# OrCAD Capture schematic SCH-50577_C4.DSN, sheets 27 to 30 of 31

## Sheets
27 26 Interface/JTAG: size C
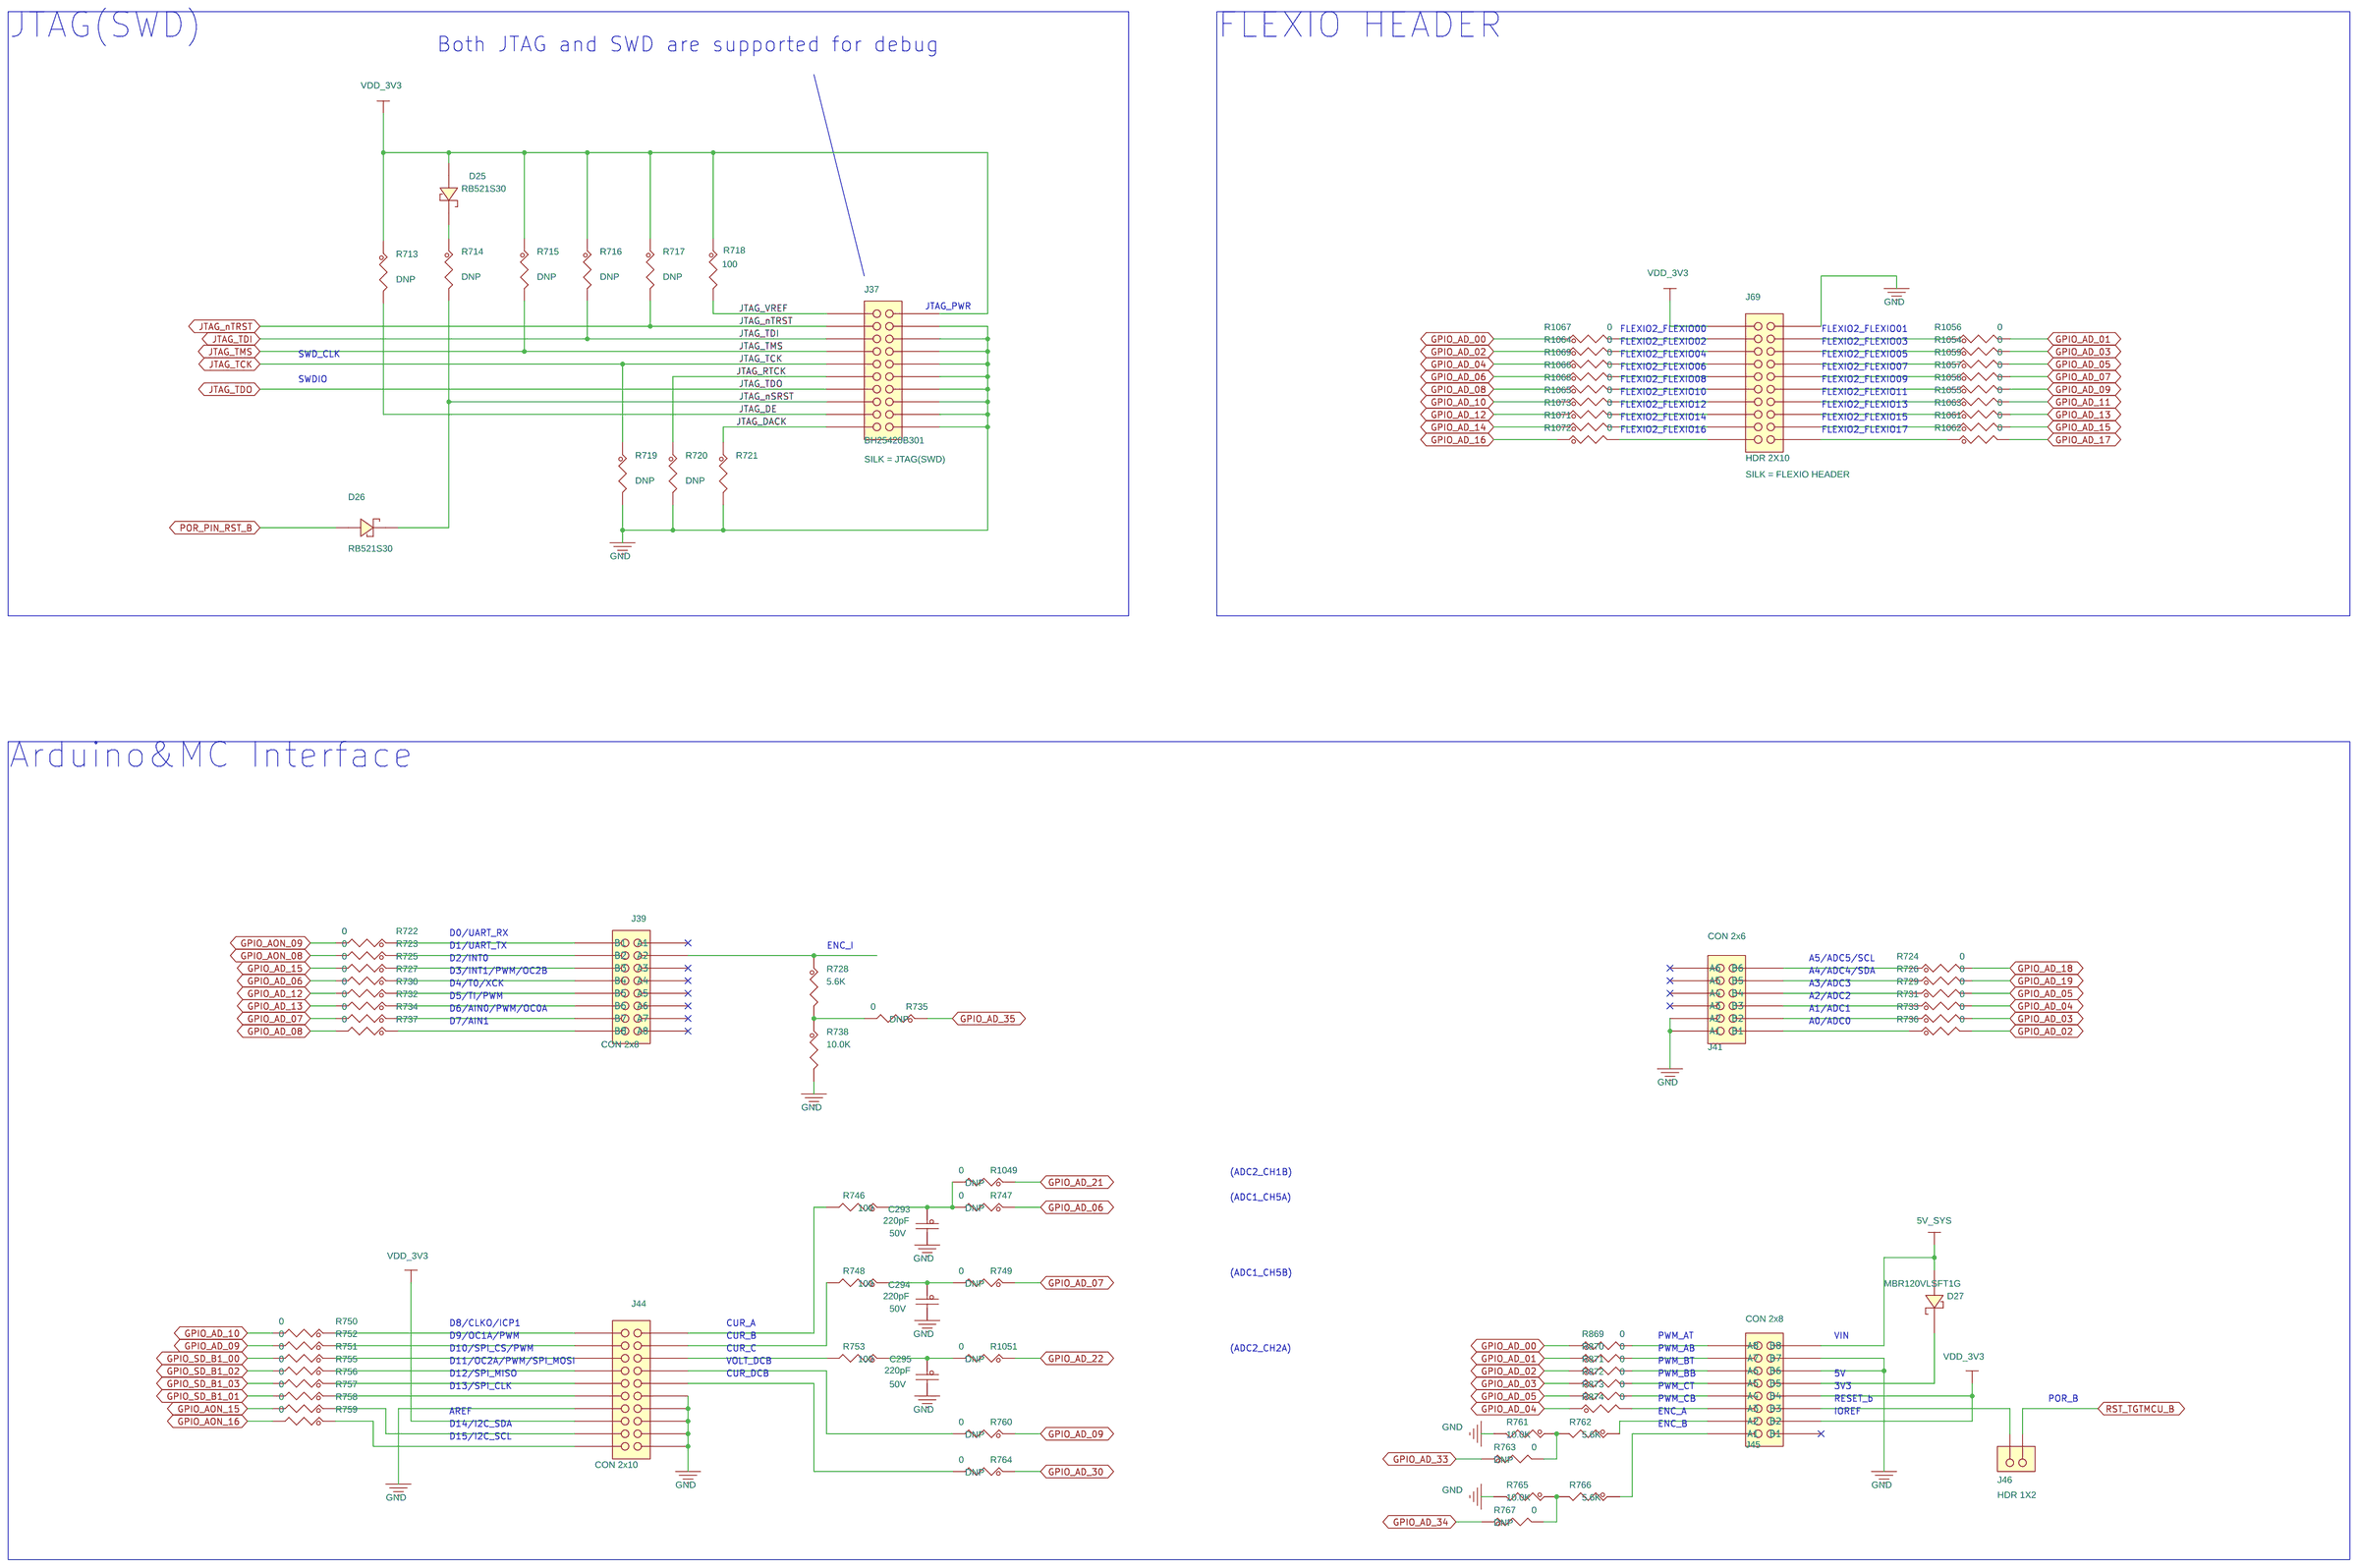
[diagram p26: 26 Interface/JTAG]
28 11 SDRAM_opt/HyperRAM: size C
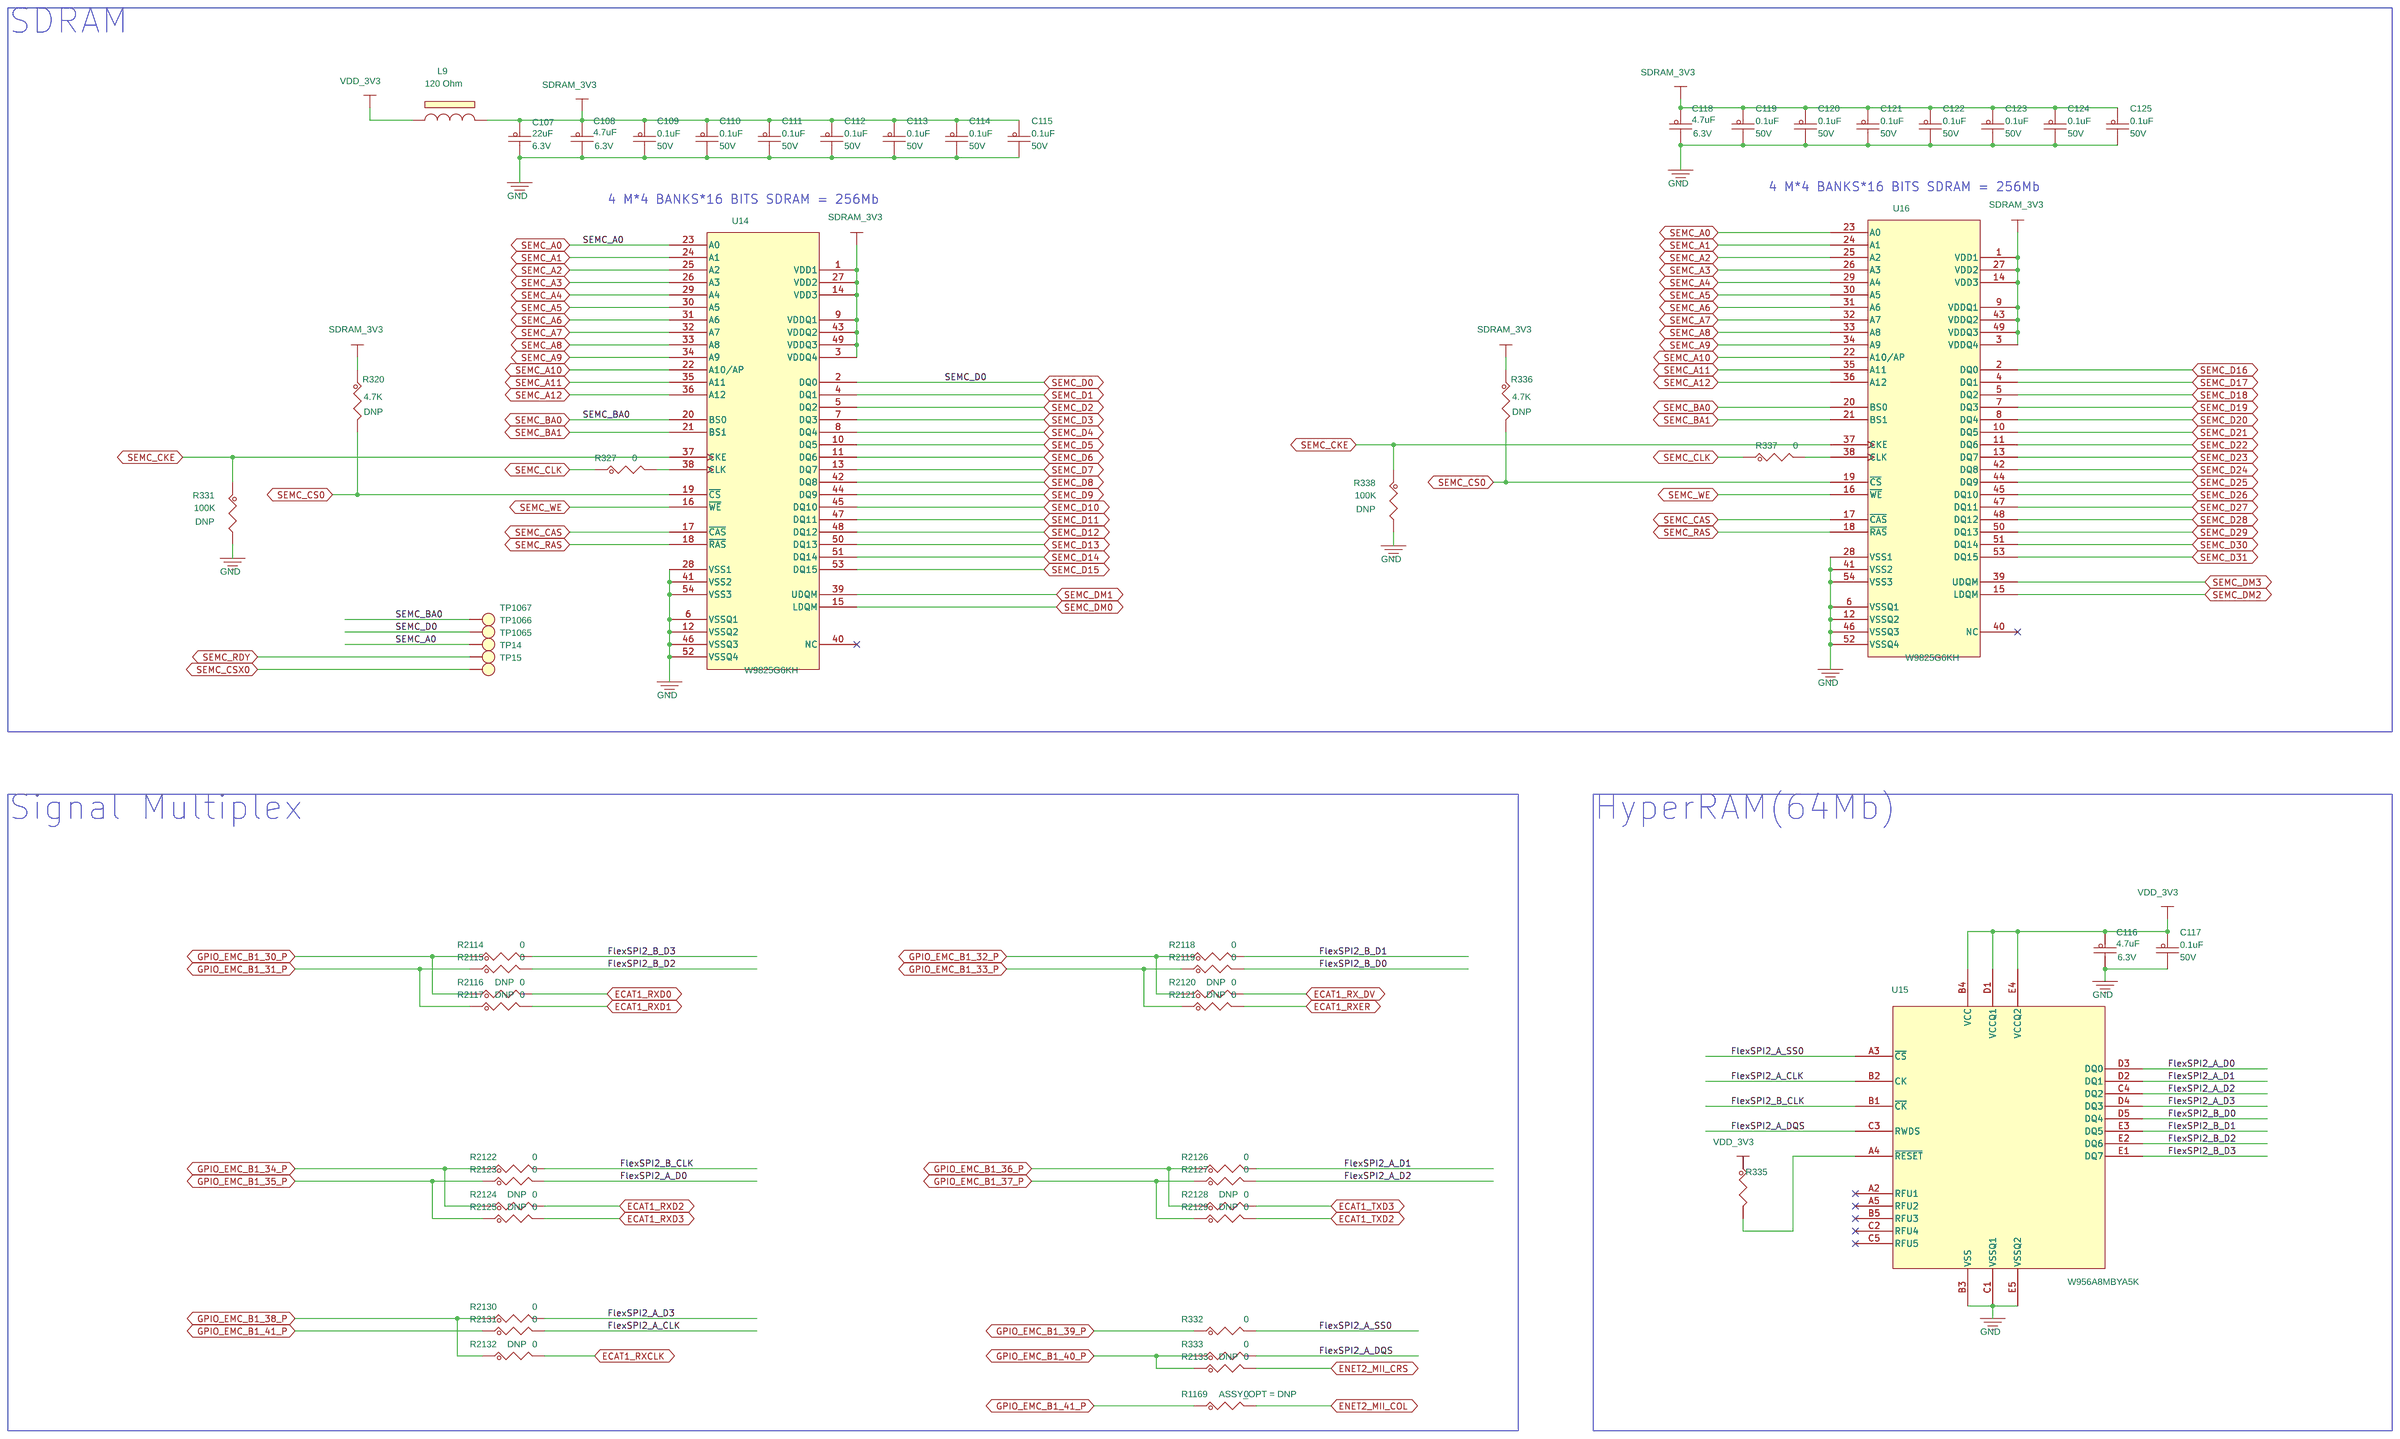
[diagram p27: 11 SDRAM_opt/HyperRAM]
29 20 RGMII/MII/RMII DC: size C; note: SCH-55220, PDF:SPF-55220
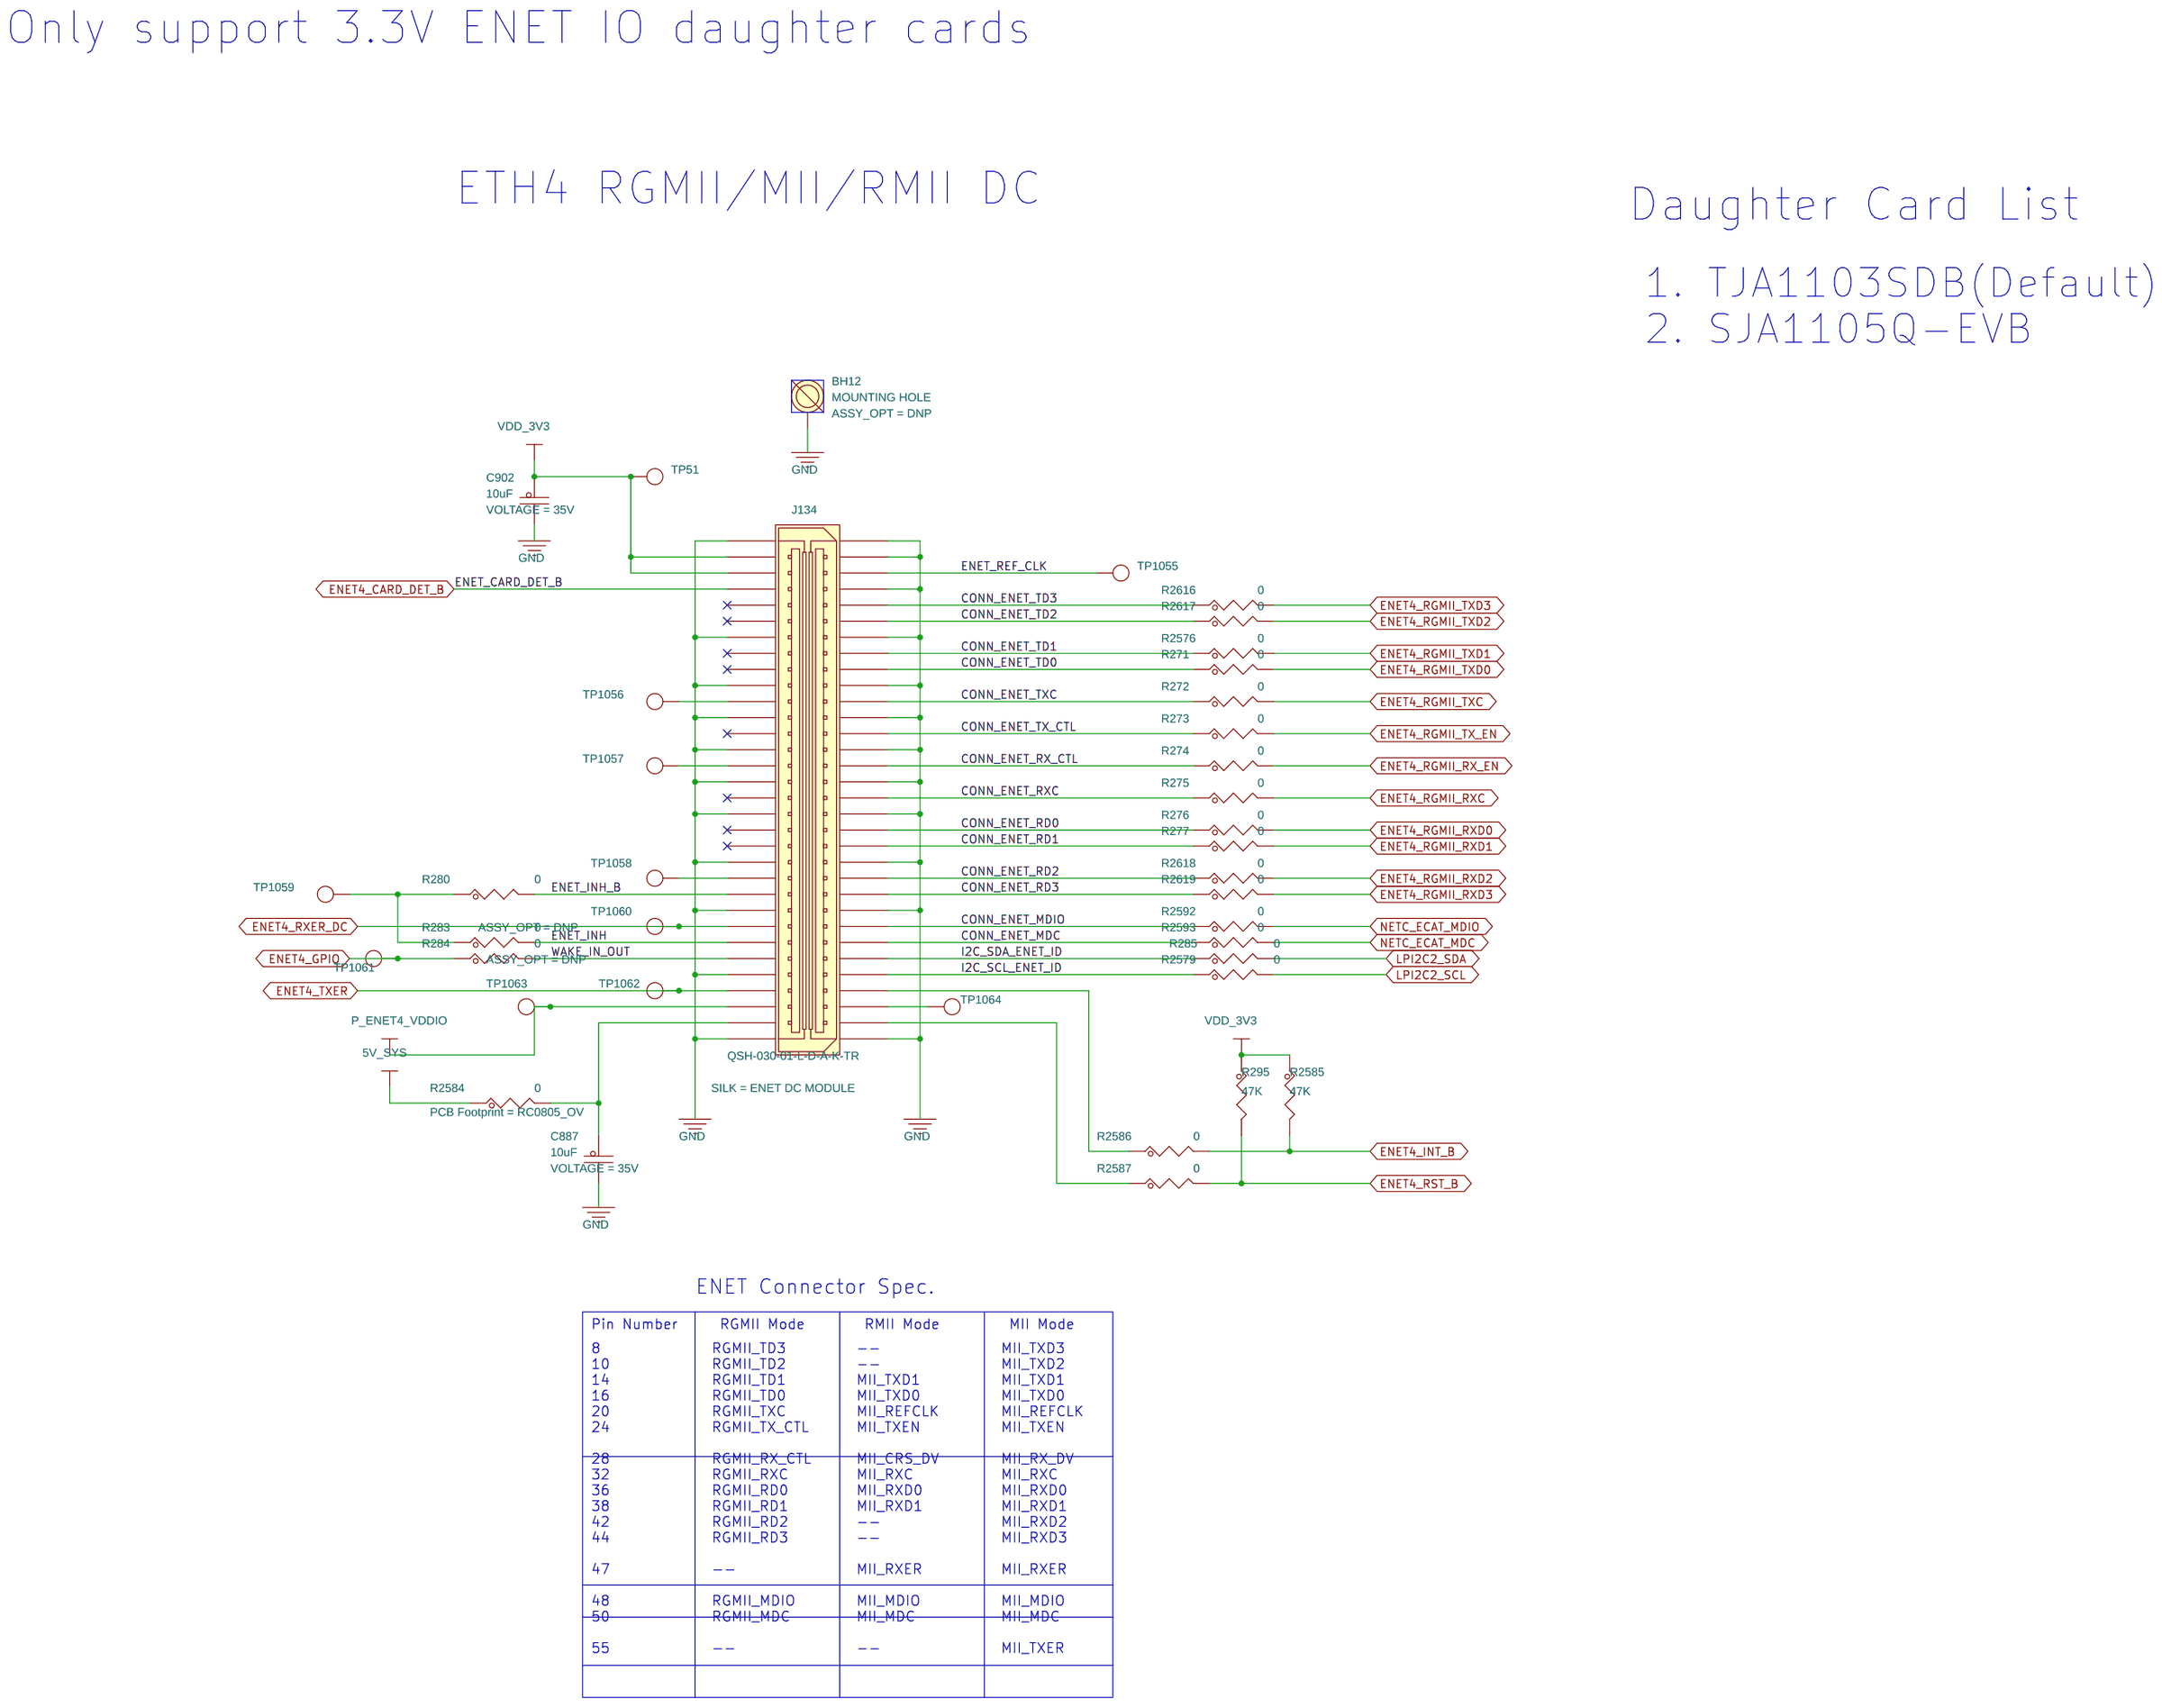
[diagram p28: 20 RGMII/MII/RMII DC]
30 19 PHY4_RMII/MII_ECAT1: size C
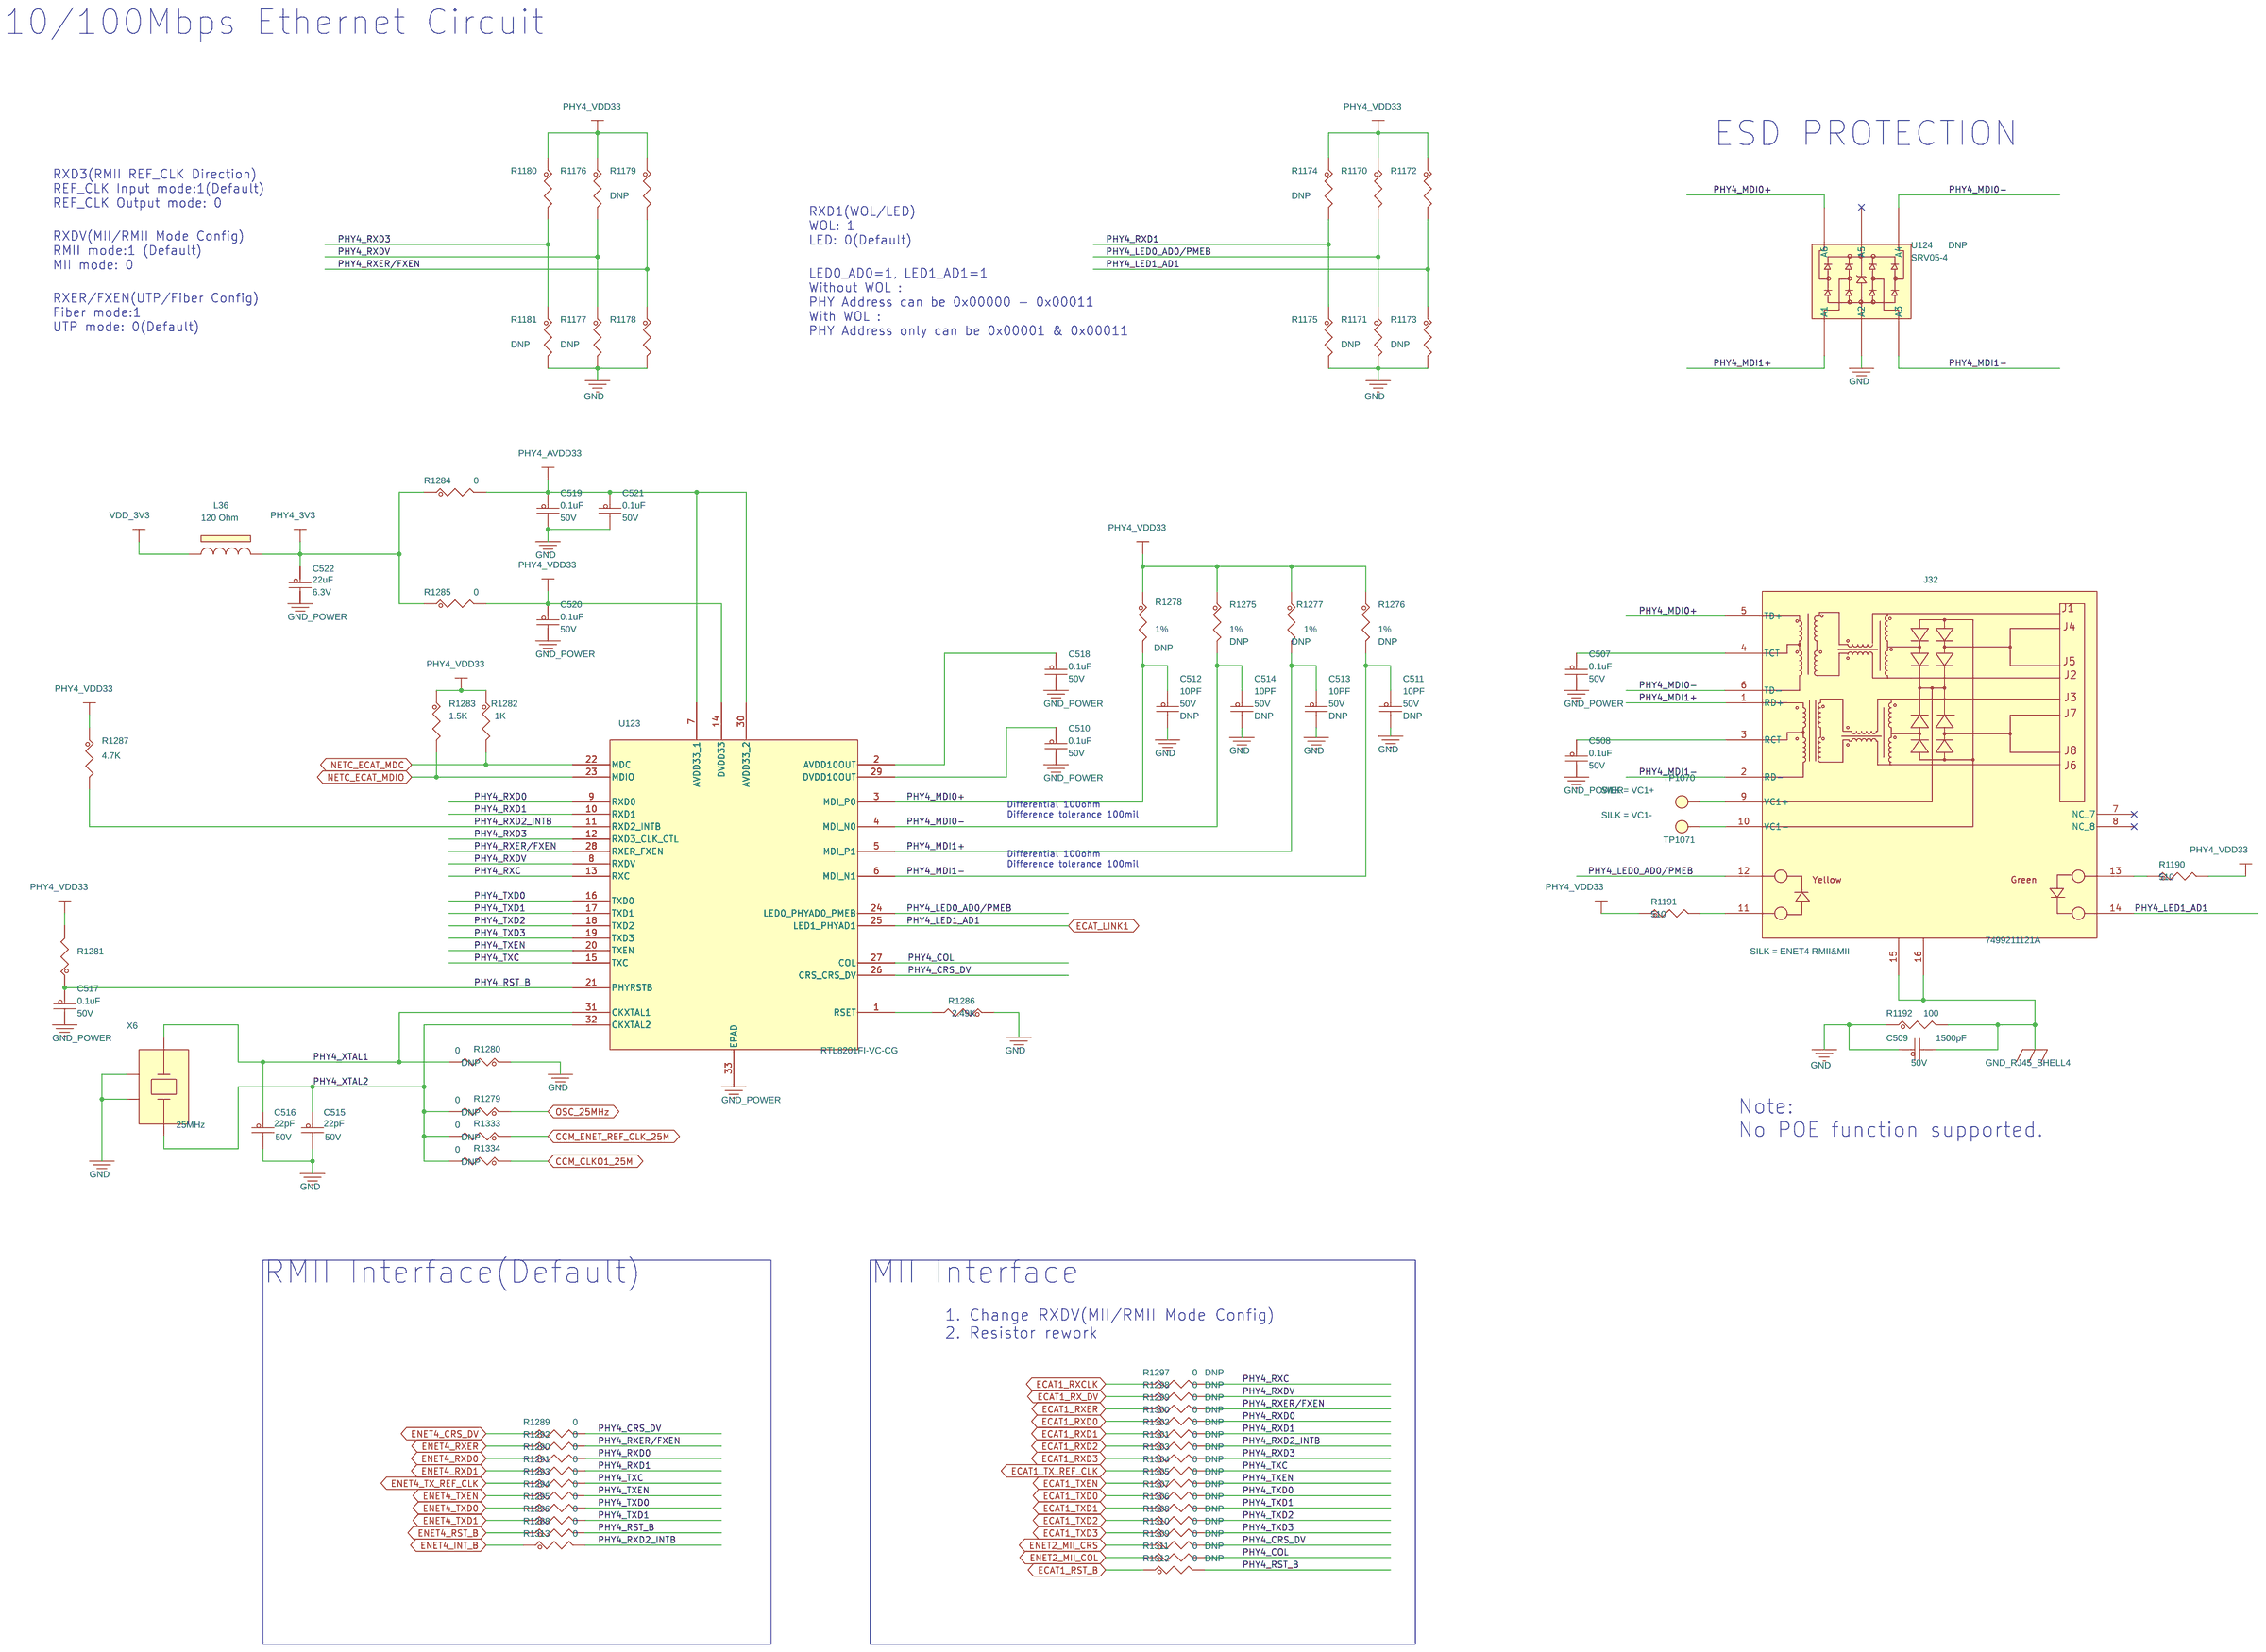
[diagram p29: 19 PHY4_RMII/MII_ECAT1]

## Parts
sheet 11 SDRAM_opt/HyperRAM
C107  22uF  [CC0603_OV]
C108  4.7uF  [cc0402_tol0p15]
C109  0.1uF  [0402_CC]
C110  0.1uF  [0402_CC]
C111  0.1uF  [0402_CC]
C112  0.1uF  [0402_CC]
C113  0.1uF  [0402_CC]
C114  0.1uF  [0402_CC]
C115  0.1uF  [0402_CC]
C116  4.7uF  [cc0402_tol0p15]
C117  0.1uF  [0402_CC]
C118  4.7uF  [cc0402_tol0p15]
C119  0.1uF  [0402_CC]
C120  0.1uF  [0402_CC]
C121  0.1uF  [0402_CC]
C122  0.1uF  [0402_CC]
C123  0.1uF  [0402_CC]
C124  0.1uF  [0402_CC]
C125  0.1uF  [0402_CC]
L9  120 Ohm  [0402_CC]
R320  4.7K  [0402_CC]
R327  0  [0402_CC]
R331  100K  [0402_CC]
R332  0  [0402_CC]
R333  0  [0402_CC]
R335  10K  [0402_CC]
R336  4.7K  [0402_CC]
R337  0  [0402_CC]
R338  100K  [0402_CC]
R1169  0  [0402_CC]
R2114  0  [0402_CC]
R2115  0  [0402_CC]
R2116  0  [0402_CC]
R2117  0  [0402_CC]
R2118  0  [0402_CC]
R2119  0  [0402_CC]
R2120  0  [0402_CC]
R2121  0  [0402_CC]
R2122  0  [0402_CC]
R2123  0  [0402_CC]
R2124  0  [0402_CC]
R2125  0  [0402_CC]
R2126  0  [0402_CC]
R2127  0  [0402_CC]
R2128  0  [0402_CC]
R2129  0  [0402_CC]
R2130  0  [0402_CC]
R2131  0  [0402_CC]
R2132  0  [0402_CC]
R2133  0  [0402_CC]
TP14  TP_35MIL  [testpoint_35mil]
TP15  TP_35MIL  [testpoint_35mil]
TP1065  TP_35MIL  [testpoint_35mil]
TP1066  TP_35MIL  [testpoint_35mil]
TP1067  TP_35MIL  [testpoint_35mil]
U14  W9825G6KH  [tsopii_54]
U15  W956A8MBYA5K  [pbga24_1_6x8mm]
U16  W9825G6KH  [tsopii_54]
sheet 19 PHY4_RMII/MII_ECAT1
C507  0.1uF  [0402_CC]
C508  0.1uF  [0402_CC]
C509  1500pF  [0402_CC]
C510  0.1uF  [0402_CC]
C511  10PF  [0402_CC]
C512  10PF  [0402_CC]
C513  10PF  [0402_CC]
C514  10PF  [0402_CC]
C515  22pF  [0402_CC]
C516  22pF  [0402_CC]
C517  0.1uF  [0402_CC]
C518  0.1uF  [0402_CC]
C519  0.1uF  [0402_CC]
C520  0.1uF  [0402_CC]
C521  0.1uF  [0402_CC]
C522  22uF  [CC0603_OV]
J32  7499211121A  [con_rj45_2led_th_a]
L36  120 Ohm  [0402_CC]
R1170  4.7K  [0402_CC]
R1171  4.7K  [0402_CC]
R1172  4.7K  [0402_CC]
R1173  4.7K  [0402_CC]
R1174  4.7K  [0402_CC]
R1175  4.7K  [0402_CC]
R1176  4.7K  [0402_CC]
R1177  4.7K  [0402_CC]
R1178  4.7K  [0402_CC]
R1179  4.7K  [0402_CC]
R1180  4.7K  [0402_CC]
R1181  4.7K  [0402_CC]
R1190  510  [RC0402_25]
R1191  510  [RC0402_25]
R1192  100  [0402_CC]
R1275  49.9  [RC0603_OV]
R1276  49.9  [RC0603_OV]
R1277  49.9  [RC0603_OV]
R1278  49.9  [RC0603_OV]
R1279  0  [0402_CC]
R1280  0  [0402_CC]
R1281  10K  [0402_CC]
R1282  1K  [0402_CC]
R1283  1.5K  [0402_CC]
R1284  0  [0402_CC]
R1285  0  [0402_CC]
R1286  2.49K  [RC0402_25]
R1287  4.7K  [0402_CC]
R1288  0  [0402_CC]
R1289  0  [0402_CC]
R1290  0  [0402_CC]
R1291  0  [0402_CC]
R1292  0  [0402_CC]
R1293  0  [0402_CC]
R1294  0  [0402_CC]
R1295  0  [0402_CC]
R1296  0  [0402_CC]
R1297  0  [0402_CC]
R1298  0  [0402_CC]
R1299  0  [0402_CC]
R1300  0  [0402_CC]
R1301  0  [0402_CC]
R1302  0  [0402_CC]
R1303  0  [0402_CC]
R1304  0  [0402_CC]
R1305  0  [0402_CC]
R1306  0  [0402_CC]
R1307  0  [0402_CC]
R1308  0  [0402_CC]
R1309  0  [0402_CC]
R1310  0  [0402_CC]
R1311  0  [0402_CC]
R1312  0  [0402_CC]
R1313  0  [0402_CC]
R1333  0  [0402_CC]
R1334  0  [0402_CC]
TP1070  TP_35MIL  [testpoint_35mil]
TP1071  TP_35MIL  [testpoint_35mil]
U123  RTL8201FI-VC-CG  [qfn32_0p5_5x5_s142ep]
U124  SRV05-4  [SOT23_S6]
X6  25MHz  [xtal4_5p2x3p4mm_sm]
sheet 20 RGMII/MII/RMII DC
BH12  MOUNTING HOLE  [mh256p130]
C887  10uF  [CC1206_OV]
C902  10uF  [CC1206_OV]
J134  QSH-030-01-L-D-A-K-TR  [CON_60S_QSH_SM_A]
R271  0  [rc0402_25]
R272  0  [rc0402_25]
R273  0  [rc0402_25]
R274  0  [rc0402_25]
R275  0  [rc0402_25]
R276  0  [rc0402_25]
R277  0  [rc0402_25]
R280  0  [rc0402_25]
R283  0  [rc0402_25]
R284  0  [rc0402_25]
R285  0  [rc0402_25]
R295  47K  [RC0402_25]
R2576  0  [rc0402_25]
R2579  0  [rc0402_25]
R2584  0  [RC0805_OV]
R2585  47K  [RC0402_25]
R2586  0  [rc0402_25]
R2587  0  [rc0402_25]
R2592  0  [rc0402_25]
R2593  0  [rc0402_25]
R2616  0  [rc0402_25]
R2617  0  [rc0402_25]
R2618  0  [rc0402_25]
R2619  0  [rc0402_25]
TP51  TPAD_020  [tpad_020]
TP1055  TPAD_020  [tpad_020]
TP1056  TPAD_020  [tpad_020]
TP1057  TPAD_020  [tpad_020]
TP1058  TPAD_020  [tpad_020]
TP1059  TPAD_020  [tpad_020]
TP1060  TPAD_020  [tpad_020]
TP1061  TPAD_020  [tpad_020]
TP1062  TPAD_020  [tpad_020]
TP1063  TPAD_020  [tpad_020]
TP1064  TPAD_020  [tpad_020]
sheet 26 Interface/JTAG
C293  220pF  [0402_CC]
C294  220pF  [0402_CC]
C295  220pF  [0402_CC]
D25  RB521S30  [SOD523]
D26  RB521S30  [SOD523]
D27  MBR120VLSFT1G  [SOD-123]
J37  BH25420B301  [hdr_2x10m_100_th]
J39  CON 2x8  [con_2x8_skt_100_th]
J41  CON 2x6  [con_skt2x6_th]
J44  CON 2x10  [con_skt2x10_th]
J45  CON 2x8  [con_2x8_skt_100_th]
J46  HDR 1X2  [HDR102]
J69  HDR 2X10  [hdr210_344h]
R713  10K  [0402_CC]
R714  10K  [0402_CC]
R715  10K  [0402_CC]
R716  10K  [0402_CC]
R717  10K  [0402_CC]
R718  100  [0402_CC]
R719  10K  [0402_CC]
R720  10K  [0402_CC]
R721  10K  [0402_CC]
R722  0  [0402_CC]
R723  0  [0402_CC]
R724  0  [0402_CC]
R725  0  [0402_CC]
R726  0  [0402_CC]
R727  0  [0402_CC]
R728  5.6K  [0402_CC]
R729  0  [0402_CC]
R730  0  [0402_CC]
R731  0  [0402_CC]
R732  0  [0402_CC]
R733  0  [0402_CC]
R734  0  [0402_CC]
R735  0  [0402_CC]
R736  0  [0402_CC]
R737  0  [0402_CC]
R738  10.0K  [0402_CC]
R746  100  [0402_CC]
R747  0  [0402_CC]
R748  100  [0402_CC]
R749  0  [0402_CC]
R750  0  [0402_CC]
R751  0  [0402_CC]
R752  0  [0402_CC]
R753  100  [0402_CC]
R755  0  [0402_CC]
R756  0  [0402_CC]
R757  0  [0402_CC]
R758  0  [0402_CC]
R759  0  [0402_CC]
R760  0  [0402_CC]
R761  10.0K  [0402_CC]
R762  5.6K  [0402_CC]
R763  0  [0402_CC]
R764  0  [0402_CC]
R765  10.0K  [0402_CC]
R766  5.6K  [0402_CC]
R767  0  [0402_CC]
R869  0  [0402_CC]
R870  0  [0402_CC]
R871  0  [0402_CC]
R872  0  [0402_CC]
R873  0  [0402_CC]
R874  0  [0402_CC]
R1049  0  [0402_CC]
R1051  0  [0402_CC]
R1054  0  [0402_CC]
R1055  0  [0402_CC]
R1056  0  [0402_CC]
R1057  0  [0402_CC]
R1058  0  [0402_CC]
R1059  0  [0402_CC]
R1061  0  [0402_CC]
R1062  0  [0402_CC]
R1063  0  [0402_CC]
R1064  0  [0402_CC]
R1065  0  [0402_CC]
R1066  0  [0402_CC]
R1067  0  [0402_CC]
R1068  0  [0402_CC]
R1069  0  [0402_CC]
R1071  0  [0402_CC]
R1072  0  [0402_CC]
R1073  0  [0402_CC]

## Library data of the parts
C107 C522 = CAP_NP: CAP CER 22uF 6.3V 20% X6S 0603; AGILE_PN: 150-79717; CAD_APPROVED: Yes; FPLIST: CC0603_OV,CC0603,0603_CC_NSP; HEIGHT: 1MM; MFG_NAME01: MURATA; MFG_PN01: GRM188C80J226ME15D; Package Size: 0603; Package Type: 180mm ReelPAPER W8P4; ROHS: Yes; Tolerance: 20%; VOLTAGE: 6.3V
C108 C116 C118 = CAP_NP: CAP CER 4.7uF 6.3V 20% X6S 0402; AGILE_PN: 150-81296; CAD_APPROVED: Yes; FPLIST: cc0402_tol0p15,cc0402_tol0p15_ov,cc0402_25_tol0p2,0402_cc_nsp; HEIGHT: 0.65MM; MFG_NAME01: MURATA; MFG_PN01: GRM155C80J475MEAA; Package Size: 0402 (1005 Metric); Package Type: SMD/SMT; ROHS: Yes; Rated Voltage: 6.3V; Temp Range: -55°C to +105°C; Tolerance: 20%; VOLTAGE: 6.3V
C109-C115 C117 C119-C125 C507 C508 C510 C517-C521 = CAP_NP: CAP CER 0.1uF 50V 10% X7R AEC-Q200 0402; AGILE_PN: 150-79461; CAD_APPROVED: Yes; FPLIST: CC0402_25,CC0402_HD,0402_CC,CC0402_18,capc0402_l; HEIGHT: 0.55MM; MFG_NAME01: MURATA; MFG_PN01: GCM155R71H104KE02D; Package Size: 0402; ROHS: Yes; Tolerance: 10%; VOLTAGE: 50V
L9 L36 = INDUCTOR_FERRITE: IND FER BEAD 120 OHM@100MHZ 0.5A 25% 0402; AGILE_PN: 180-77771; CAD_APPROVED: Yes; FPLIST: IND_0402,0402_CC; HEIGHT: 0.55MM; MFG_NAME01: MURATA; MFG_PN01: BLM15AG121SN1D; PART_TYPE: FERRITE\BEAD; Package Size: 0402; ROHS: Yes; Tolerance: 25%
R320 R336 = RES: RES MF 4.7K 1/16W 5% 0402; AGILE_PN: 470-75626; ASSY_OPT: DNP; CAD_APPROVED: Yes; FPLIST: RC0402_25,RC0402_HD,0402_CC; HEIGHT: 0.41mm; MFG_NAME01: NIC COMPONENTS CORP; MFG_PN01: NRCL04J472TRF; ROHS: Yes; Tolerance: 5%
R327 R337 R869-R874 R1284 R1285 R1288 R1290-R1296 R1313 = RES: RES MF ZERO OHM 1/16W 5% 0402; AGILE_PN: 470-75394; CAD_APPROVED: Yes; FPLIST: RC0402_25,RC0402_HD,RC0402_X2,0402_CC; HEIGHT: 0.45 MM; MFG_NAME01: ROHM; MFG_PN01: MCR01MZPJ000; ROHS: Yes; Tolerance: 5%; VOLTAGE: 1/16W
R331 R338 = RES: RES MF 100K 1/16W 5% 0402; AGILE_PN: 470-75597; ASSY_OPT: DNP; CAD_APPROVED: Yes; FPLIST: RC0402_25,RC0402_HD,0402_CC; HEIGHT: 0.40 MM; MFG_NAME01: VENKEL COMPANY; MFG_PN01: CR0402-16W-104JT; ROHS: Yes; Temp Range: -55C to +155C; Temp_Range: -55C to +155C; Tolerance: 5%; VOLTAGE: 50V
R332 R333 R722-R727 R729-R734 R736 R737 R750-R752 R755-R759 R1054-R1059 R1061-R1069 R1071-R1073 R1289 R2114 R2115 R2118 R2119 R2122 R2123 R2126 R2127 R2130 R2131 = RES: RES MF ZERO OHM 1/16W 5% 0402; AGILE_PN: 470-75394; CAD_APPROVED: Yes; FPLIST: RC0402_25,RC0402_HD,RC0402_X2,0402_CC; HEIGHT: 0.45 MM; MFG_NAME01: YAGEO AMERICA; MFG_PN01: RC0402JR-070RL; ROHS: Yes; Tolerance: 5%; VOLTAGE: 1/16W
R335 R1281 = RES: RES MF 10K 1/16W 5% 0402; AGILE_PN: 470-75557; CAD_APPROVED: Yes; FPLIST: RC0402_25,RC0402_HD,0402_CC; HEIGHT: 0.4 MM; MFG_NAME01: VISHAY INTERTECHNOLOGY; MFG_PN01: CRCW040210K0JNED; ROHS: Yes; TOL: 5%; Tolerance: 5%
R735 R747 R749 R760 R763 R764 R767 R1049 R1051 R1169 R2116 R2117 R2120 R2121 R2124 R2125 R2128 R2129 R2132 R2133 = RES: RES MF ZERO OHM 1/16W 5% 0402; AGILE_PN: 470-75394; ASSY_OPT: DNP; CAD_APPROVED: Yes; FPLIST: RC0402_25,RC0402_HD,RC0402_X2,0402_CC; HEIGHT: 0.45 MM; MFG_NAME01: YAGEO AMERICA; MFG_PN01: RC0402JR-070RL; ROHS: Yes; Tolerance: 5%; VOLTAGE: 1/16W
TP14 TP15 TP1065-TP1067 = T_POINT_R: TEST POINT PAD .035 SMT, no part to order; AGILE_PN: 510-75618; CAD_APPROVED: Yes; HEIGHT: 0.1MM; ROHS: Yes
U14 U16 = W9825G6KH_54P: IC MEM SDRAM 4Mx16bitsx4 200MHZ/CL3 or 133MHz/CL2 5mA 3.3V TSOPII-54; 3D_Mechanical_Footprint_File: ftp://fcl.am.freescale.net/ALLEGRO/step/tsopii_54.STEP; AGILE_PN: 334-77943; CAD_APPROVED: yes; HEIGHT: 1.2MM; MFG_NAME01: WINBOND ELECTRONICS CORP; MFG_PN01: W9825G6KH-5J; ROHS: Yes; Temp Range: -40C to +105C; VOLTAGE: 3.3V
U15 = W959D8NFYA5_TFBGA24: IC MEM HYPER RAM 64MB 200MHz 3V TFBGA24; 3D_Mechanical_Footprint_File: http://fcl.am.freescale.net/ALLEGRO/step/pbga24_1_6x8mm.STEP; AGILE_PN: 334-82936; CAD_APPROVED: Yes; HEIGHT: 1.20 MM; MFG_NAME01: WINBOND ELECTRONICS CORP; ROHS: Yes; Temp Range: -40 °C - +105 °C
C509 = CAP_NP: CAP CER 1500PF 50V 10% X7R 0402; AGILE_PN: 150-76273; CAD_APPROVED: Yes; FPLIST: CC0402_25,CC0402_HD,0402_CC; HEIGHT: 0.55MM; MFG_NAME01: AVX; MFG_PN01: 04025C152KAT2A; ROHS: Yes; Tolerance: 10%; VOLTAGE: 50V
C511-C514 = CAP_NP: CAP CER 10PF 50V 5% C0G 0402; AGILE_PN: 150-75265; ASSY_OPT: DNP; CAD_APPROVED: YES; FPLIST: CC0402_25,CC0402_HD,0402_CC; HEIGHT: 0.635MM; MFG_NAME01: AVX; MFG_PN01: 04025A100JAT2A; Package Size: 0402; Package Type: 7; ROHS: Yes; TOL: 5%; Tolerance: 5%; VOLTAGE: 50V
C515 C516 = CAP_NP: CAP CER 22pF 50V 2% C0G HIGH-Q 0402; AGILE_PN: 150-79896; CAD_APPROVED: Yes; FPLIST: CC0402_25,CC0402_HD,0402_CC,capc0402_l; HEIGHT: 0.55MM; MFG_NAME01: MURATA; MFG_PN01: GJM1555C1H220GB01D; Package Size: 0402; Package Type: 180mm Reel PAPER W8P2; ROHS: Yes; Temp Range: -55 to +125°C; Tolerance: 2%; VOLTAGE: 50V
J32 = RJ45_7499211121A: CON 14 RJ-45 RA SHLD TH G/Y LEDS 50MIL SP 549H AU 140L; AGILE_PN: 210-81885; CAD_APPROVED: Yes; HEIGHT: 13.95MM; MFG_NAME01: WURTH ELEKTRONIK EISOS GMBH & CO. KG (ELECTRONIC & ELECTROMEHANICAL COMP); ROHS: Yes; SILK: ENET4 RMII&MII; Temp Range: -40 to 85C; Temp_Range: -40 to 85C
R1170 R1172 R1175 R1176 R1178 R1180 = RES: RES MF 4.70K 1/16W 1% 0402; AGILE_PN: 470-75418; CAD_APPROVED: Yes; FPLIST: RC0402_25,RC0402_HD,0402_CC; HEIGHT: 0.4mm; MFG_NAME01: WALSIN TECHNOLOGY CORP.; MFG_PN01: WR04X4701FTL; ROHS: Yes; Tolerance: 1%; VOLTAGE: 1/16W
R1171 R1173 R1174 R1177 R1179 R1181 = RES: RES MF 4.70K 1/16W 1% 0402; AGILE_PN: 470-75418; ASSY_OPT: DNP; CAD_APPROVED: Yes; FPLIST: RC0402_25,RC0402_HD,0402_CC; HEIGHT: 0.4mm; MFG_NAME01: WALSIN TECHNOLOGY CORP.; MFG_PN01: WR04X4701FTL; ROHS: Yes; Tolerance: 1%; VOLTAGE: 1/16W
R1190 R1191 = RES: RES MF 510 OHM 1/16W 1% AEC-Q200 0402; AGILE_PN: 470-80725; CAD_APPROVED: Yes; FPLIST: RC0402_25,RC0402_HD,0402_CC; HEIGHT: 0.4 MM; MFG_NAME01: VISHAY INTERTECHNOLOGY; MFG_PN01: CRCW0402510RFKED; ROHS: Yes; Tolerance: 1%
R746 R748 R753 R1192 = RES: RES MF 100 OHM 1/16W 5% 0402; AGILE_PN: 470-75591; CAD_APPROVED: Yes; FPLIST: RC0402_25,RC0402_HD,RC0402_X2,0402_CC; HEIGHT: 0.45mm; MFG_NAME01: NIC COMPONENTS CORP; MFG_PN01: NRCL04J101TRF; ROHS: Yes; Tolerance: 5%
R1275-R1278 = RES: RES MF 49.9 OHM 1/10W 1% 0603; AGILE_PN: 470-75432; ASSY_OPT: DNP; CAD_APPROVED: Yes; FPLIST: RC0603_OV,RC0603,0603_CC; HEIGHT: 0.55 MM; MFG_NAME01: BOURNS; MFG_PN01: CR0603-FX-49R9ELF; ROHS: Yes; TOL: 1%; Tolerance: 1%
R1279 R1280 R1297-R1312 R1333 R1334 = RES: RES MF ZERO OHM 1/16W 5% 0402; AGILE_PN: 470-75394; ASSY_OPT: DNP; CAD_APPROVED: Yes; FPLIST: RC0402_25,RC0402_HD,RC0402_X2,0402_CC; HEIGHT: 0.45 MM; MFG_NAME01: ROHM; MFG_PN01: MCR01MZPJ000; ROHS: Yes; Tolerance: 5%; VOLTAGE: 1/16W
R1282 = RES: RES MF 1.0K 1/16W 5% 0402; AGILE_PN: 470-75555; CAD_APPROVED: Yes; FPLIST: RC0402_25,RC0402_HD,RC0402_X2,0402_CC; HEIGHT: 0.41mm; MFG_NAME01: VISHAY INTERTECHNOLOGY; MFG_PN01: CRCW04021K00JNED; ROHS: Yes; Tolerance: 5%
R1283 = RES: RES MF 1.5K 1/16W 5% 0402; AGILE_PN: 470-76303; CAD_APPROVED: Yes; FPLIST: RC0402_25,RC0402_HD,0402_CC; HEIGHT: 0.40 MM; MFG_NAME01: VISHAY INTERTECHNOLOGY; MFG_PN01: CRCW04021K50JNED; ROHS: Yes; Tolerance: 5%; VOLTAGE: 1/16W
R1286 = RES: RES MF 2.49K 1/16W 1% 0402; AGILE_PN: 470-76080; CAD_APPROVED: Yes; FPLIST: RC0402_25,RC0402_HD,0402_CC; HEIGHT: 0.4 MM; MFG_NAME01: BOURNS; MFG_PN01: CR0402-FX-2491GLF; ROHS: Yes; Tolerance: 1%
R1287 = RES: RES MF 4.7K 1/16W 5% 0402; AGILE_PN: 470-75626; CAD_APPROVED: Yes; FPLIST: RC0402_25,RC0402_HD,0402_CC; HEIGHT: 0.41mm; MFG_NAME01: NIC COMPONENTS CORP; MFG_PN01: NRCL04J472TRF; ROHS: Yes; Tolerance: 5%
TP1070 = T_POINT_R: TEST POINT PAD .035 SMT, no part to order; AGILE_PN: 510-75618; CAD_APPROVED: Yes; HEIGHT: 0.1MM; ROHS: Yes; SILK: VC1+
TP1071 = T_POINT_R: TEST POINT PAD .035 SMT, no part to order; AGILE_PN: 510-75618; CAD_APPROVED: Yes; HEIGHT: 0.1MM; ROHS: Yes; SILK: VC1-
U123 = RTL8201FI: IC SINGLE CHIP/PORT 10/100M ETHERNET 2.97-3.63V QFN32; AGILE_PN: 312-83298; CAD_APPROVED: Yes; HEIGHT: 1MM; MFG_NAME01: REALTEK SEMICONDUCTOR; ROHS: Yes; Temp Range: -40C to +85C; VOLTAGE: 2.97-3.63V
U124 = SRV05-4: DIODE TVS ARRAY 12A 5V 300W SOT23_S6; AGILE_PN: 480-75205; ASSY_OPT: DNP; CAD_APPROVED: Yes; HEIGHT: 1.45mm; MFG_NAME01: SEMTECH CORP; MFG_PN01: SRV05-4.TCT; ROHS: Yes; Rated Voltage: 5V; VOLTAGE: 5V
X6 = XTAL_13: XTAL 25MHz 13PF 5x3.2mm SMT; AGILE_PN: 230-78201; CAD_APPROVED: Yes; EN: 108-1-00013; HEIGHT: 1MM; MFG_NAME01: CTS; MFG_PN01: 405C35B25M00000; ROHS: Yes; Temp Range: -20C to +70C; Temp_Range: -20C to +70C
BH12 = MOUNT_HOLE: MOUNTING HOLE DRILL 130 PAD 256 PLATED TH, NO PART TO ORDER; AGILE_PN: 280-76491; ASSY_OPT: DNP; CAD_APPROVED: Yes; HEIGHT: 0.1MM; ROHS: Yes
C887 C902 = CAP_NP: CAP CER 10uF 35V 10% X7R AEC-Q200 1206; AGILE_PN: 150-80299; CAD_APPROVED: Yes; FPLIST: CC1206_OV,CC1206,1206_CC; HEIGHT: 1.9MM; MFG_NAME01: TDK; MFG_PN01: CGA5L1X7R1V106K160AC; Package Size: 1206; ROHS: Yes; Temp Range: -55°C ~ 125°C; Tolerance: 10%; VOLTAGE: 35V
J134 = QSH030: CON 2X30 SKT SMT 0.5MM SP 120H AU  MOUNTING HOLES TO MATE CABLE HQCD-030-15.00-TBL-TBR-1-SDB; 3D_Mechanical_Footprint_File: ftp://fcl.am.freescale.net/ALLEGRO/step/con_60s_qsh_sm.STEP; AGILE_PN: 211-75161; CAD_APPROVED: Yes; EN: 201-1-00859; FPLIST: CON_60S_QSH_SM_A,CON_60S_QSH_SM; HEIGHT: 3.25 MM; MFG_NAME01: SAMTEC; MFG_PN01: QSH-030-01-L-D-A_; Package Size: SMD-60; Package Type: SMD; ROHS: Yes; SILK: ENET DC MODULE; VOLTAGE: 125V
R271-R277 R280 R285 R2576 R2579 R2586 R2587 R2592 R2593 R2616-R2619 = RES: RES MF ZERO OHM 1/8W -- AEC-Q200 0402; AGILE_PN: 470-82894; CAD_APPROVED: Yes; FPLIST: rc0402_25,rc0402_hd,0402_cc; HEIGHT: 0.4 MM; MFG_NAME01: VISHAY; MFG_PN01: RCC04020000Z0ED; Package Size: 0402 [1005 Metric]; Package Type: SMD/SMT; ROHS: Yes; Temp Range: -55 °C to +155 °C
R283 R284 = RES: RES MF ZERO OHM 1/8W -- AEC-Q200 0402; AGILE_PN: 470-82894; ASSY_OPT: DNP; CAD_APPROVED: Yes; FPLIST: rc0402_25,rc0402_hd,0402_cc; HEIGHT: 0.4 MM; MFG_NAME01: VISHAY; MFG_PN01: RCC04020000Z0ED; Package Size: 0402 [1005 Metric]; Package Type: SMD/SMT; ROHS: Yes; Temp Range: -55 °C to +155 °C
R295 R2585 = RES: RES MF 47K 1/10W 5% AEC-Q200 0402; AGILE_PN: 470-82117; CAD_APPROVED: Yes; FPLIST: RC0402_25,RC0402_HD,0402_CC; HEIGHT: 0.4 MM; MFG_NAME01: KOA SPEER; MFG_PN01: RK73B1ETTP473J; ROHS: Yes; Temp Range: -55&#8451; to 155&#8451;; Tolerance: 5%
R2584 = RES: RES MF ZERO OHM JUMPER 1/2W AEC-Q200 0805; AGILE_PN: 470-81272; CAD_APPROVED: Yes; FPLIST: RC0805_OV,RC0805,0805_CC; HEIGHT: 0.6MM; MFG_NAME01: VISHAY INTERTECHNOLOGY; MFG_PN01: CRCW08050000Z0EAHP; ROHS: Yes; Temp Range: -55 °C to +155 °C; VOLTAGE: 150V
TP51 TP1055-TP1064 = TestLoop: TEST POINT PAD 0.5MM DIA SMT, NO PART TO ORDER; AGILE_PN: 211-77484; ASSY_OPT: DNP; CAD_APPROVED: Yes; HEIGHT: 0.1MM; ROHS: Yes
C293-C295 = CAP_NP: CAP CER 220PF 50V 10% X7R 0402; AGILE_PN: 150-75829; CAD_APPROVED: Yes; FPLIST: CC0402_25,CC0402_HD,0402_CC; HEIGHT: 0.55MM; MFG_NAME01: KEMET; MFG_PN01: C0402C221K5RAC; ROHS: Yes; Tolerance: 10%; VOLTAGE: 50V
D25 D26 = DIODE_SCHTKY: DIODE SCH RECT 200MA 30V AEC-Q101 SOD-523; AGILE_PN: 480-79672; CAD_APPROVED: Yes; HEIGHT: 0.65MM; MFG_NAME01: NEXPERIA; MFG_PN01: RB521S30,115; ROHS: Yes; VOLTAGE: 30V
D27 = DIODE_SCHTKY: DIODE SCH RECT 1A 20V SMT; AGILE_PN: 480-75997; CAD_APPROVED: Yes; HEIGHT: 1MM; MFG_NAME01: ON SEMICONDUCTOR; ROHS: Yes; VOLTAGE: 20V
J37 = CONN_HDR_10X2: CON 2X10 PLUG SHRD TH 100MIL CTR 366H AU 118L; AGILE_PN: 210-80775; CAD_APPROVED: Yes; HEIGHT: 9.3MM; MFG_NAME01: SHENZHEN ATOM TECHNOLOGY CO.,LTD; Package Type: TH; ROHS: Yes; SILK: JTAG(SWD)
J39 J45 = CONN_HDR_8X2: CON 2X8 SKT SHRD TH 100MIL CTR 345H AU 126L; AGILE_PN: 210-81775; CAD_APPROVED: Yes; HEIGHT: 8.75MM; MFG_NAME01: ANYTRONIC CORPORATION LIMITED; MFG_PN01: 08010S31611-29RF; ROHS: Yes; Temp Range: -40 to +105C; Temp_Range: -40 to +105C
J41 = CONN_HDR_6X2: CON 2X6 SKT SHRD TH 100MIL CTR 345H AU 126L; AGILE_PN: 210-81774; CAD_APPROVED: Yes; HEIGHT: 8.75MM; MFG_NAME01: ANYTRONIC CORPORATION LIMITED; MFG_PN01: 08010S31211-29RF; ROHS: Yes; Temp Range: -40 to +105C; Temp_Range: -40 to +105C
J44 = CONN_HDR_10X2: CON 2X10 SKT SHRD TH 100MIL CTR 345H AU 126L; AGILE_PN: 210-81776; CAD_APPROVED: Yes; HEIGHT: 8.75MM; MFG_NAME01: ANYTRONIC CORPORATION LIMITED; MFG_PN01: 08010S32011-29RF; ROHS: Yes; Temp Range: -40 to +105C; Temp_Range: -40 to +105C
J46 = CONN_HDR_2X1: HDR 1X2 TH 100MIL SP 339H AU 98L; 3D_Mechanical_Footprint_File: ftp://fcl.am.freescale.net/ALLEGRO/step/hdr102_95l.STEP; AGILE_PN: 210-81490; CAD_APPROVED: Yes; HEIGHT: 8.59MM; MFG_NAME01: ANYTRONIC CORPORATION LIMITED; MFG_PN01: 0901S0202011N9T-31RF; ROHS: Yes; Temp Range: -55°C to +105°C; Temp_Range: -55°C to +105°C
J69 = CONN_HDR_10X2: HDR 2X10 TH 100MIL CTR 344H AU 118L; 3D_Mechanical_Footprint_File: ftp://fcl.am.freescale.net/ALLEGRO/step/hdr210_344h.STEP; AGILE_PN: 210-80473; CAD_APPROVED: Yes; FPLIST: hdr210_344h,hdr210; HEIGHT: 8.74MM; MFG_NAME01: WURTH ELEKTRONIK EISOS GMBH & CO. KG (ELECTRONIC & ELECTROMEHANICAL COMP); MFG_PN01: 61302021121; ROHS: Yes; SILK: FLEXIO HEADER; Temp Range: -40°C to + 105°C
R713-R717 R719 R720 = RES: RES MF 10K 1/16W 5% 0402; AGILE_PN: 470-75557; ASSY_OPT: DNP; CAD_APPROVED: Yes; FPLIST: RC0402_25,RC0402_HD,0402_CC; HEIGHT: 0.4 MM; MFG_NAME01: VISHAY INTERTECHNOLOGY; MFG_PN01: CRCW040210K0JNED; ROHS: Yes; Tolerance: 5%
R718 = RES: RES MF 100 OHM 1/16W 1% 0402; AGILE_PN: 470-30454; CAD_APPROVED: Yes; FPLIST: RC0402_25,RC0402_HD,0402_CC; HEIGHT: 0.4 MM; MFG_NAME01: THYE MING TECH CO LTD; MFG_PN01: CR-02FL6--100R; ROHS: Yes; Tolerance: 1%; VOLTAGE: 50V
R721 = RES: RES MF 10K 1/16W 5% 0402; AGILE_PN: 470-75557; CAD_APPROVED: Yes; FPLIST: RC0402_25,RC0402_HD,0402_CC; HEIGHT: 0.4 MM; MFG_NAME01: VISHAY INTERTECHNOLOGY; MFG_PN01: CRCW040210K0JNED; ROHS: Yes; Tolerance: 5%
R728 R762 R766 = RES: RES MF 5.6K  1/16W 1% 0402; AGILE_PN: 470-30919; CAD_APPROVED: Yes; FPLIST: RC0402_25,RC0402_HD,0402_CC; HEIGHT: 0.40 MM; MFG_NAME01: YAGEO AMERICA; MFG_PN01: RC0402FR-075K6L; ROHS: Yes; Temp Range: -55°C ~ 155°C; Temp_Range: -55°C ~ 155°C; Tolerance: 1%; VOLTAGE: 50V
R738 R761 R765 = RES: RES MF 10.0K 1/16W 1% 0402; AGILE_PN: 470-80574; CAD_APPROVED: Yes; FPLIST: RC0402_25,RC0402_HD,0402_CC; HEIGHT: 0.4MM; MFG_NAME01: WALSIN TECHNOLOGY CORP.; MFG_PN01: WR04X1002FTL; ROHS: Yes; Tolerance: 1%

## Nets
5V_SYS: D27.A J45.16(B8) R2584.1 ; also on sheet 5 6 14 19 20 24 25 26
GND: BH12.1 C107.2 C108.2 C109.2 C110.2 C111.2 C112.2 C113.2 C114.2 C115.2 C116.2 C117.2 C118.2 C119.2 C120.2 C121.2 C122.2 C123.2 C124.2 C125.2 C293.2 C294.2 C295.2 C507.2 C508.2 C509.1 C510.2 C511.2 C512.2 C513.2 C514.2 C515.2 C516.2 C517.2 C518.2 C519.2 C520.2 C521.2 C522.2 C887.2 C902.2 J37.4 J37.6 J37.8 J37.10 J37.12 J37.14 J37.16 J37.18 J37.20 J41.1(A1) J41.3(A2) J44.11 J44.13 J44.14 J44.15 J44.17 J44.19 J45.12(B6) J45.14(B7) J69.2 J134.2 J134.6 J134.11 J134.12 J134.17 J134.18 J134.21 J134.22 J134.25 J134.26 J134.29 J134.30 J134.33 J134.34 J134.39 J134.40 J134.45 J134.46 J134.53 J134.SH1 J134.SH2 J134.SH3 J134.SH4 R331.2 R338.2 R719.2 R720.2 R721.2 R738.2 R761.2 R765.2 R1171.2 R1173.2 R1175.2 R1177.2 R1178.2 R1181.2 R1192.1 R1280.1 R1286.1 U14.6(VSSQ1) U14.12(VSSQ2) U14.28(VSS1) U14.41(VSS2) U14.46(VSSQ3) U14.52(VSSQ4) U14.54(VSS3) U15.B3(VSS) U15.C1(VSSQ1) U15.E5(VSSQ2) U16.6(VSSQ1) U16.12(VSSQ2) U16.28(VSS1) U16.41(VSS2) U16.46(VSSQ3) U16.52(VSSQ4) U16.54(VSS3) U123.33(EPAD) U124.2(A2) X6.2 X6.4 ; also on sheet 2 5 6 7 8 9 10 11 12 13 14 15 16 17 18 19 20 21 22 23 24 25 26 31
GND_RJ45_SHELL4: C509.2 J32.15 J32.16 R1192.2
CCM_CLKO1_25M: R1334.1 ; also on sheet 9 31
CCM_ENET_REF_CLK_25M: R1333.1 ; also on sheet 8 31
CONN_ENET_MDC: J134.50 R2593.1
CONN_ENET_MDIO: J134.48 R2592.1
CONN_ENET_RD0: J134.36 R276.1
CONN_ENET_RD1: J134.38 R277.1
CONN_ENET_RD2: J134.42 R2618.1
CONN_ENET_RD3: J134.44 R2619.1
CONN_ENET_RX_CTL: J134.28 R274.1
CONN_ENET_RXC: J134.32 R275.1
CONN_ENET_TD0: J134.16 R271.1
CONN_ENET_TD1: J134.14 R2576.1
CONN_ENET_TD2: J134.10 R2617.1
CONN_ENET_TD3: J134.8 R2616.1
CONN_ENET_TX_CTL: J134.24 R273.1
CONN_ENET_TXC: J134.20 R272.1
ECAT1_RST_B: R1312.1 ; also on sheet 8
ECAT1_RX_DV: R1298.1 R2120.2
ECAT1_RXCLK: R1297.1 R2132.2
ECAT1_RXD0: R1300.1 R2116.2
ECAT1_RXD1: R1302.1 R2117.2
ECAT1_RXD2: R1301.1 R2124.2
ECAT1_RXD3: R1303.1 R2125.2
ECAT1_RXER: R1299.1 R2121.2
ECAT1_TX_REF_CLK: R1304.1 ; also on sheet 17
ECAT1_TXD0: R1307.1 ; also on sheet 17
ECAT1_TXD1: R1306.1 ; also on sheet 17
ECAT1_TXD2: R1308.1 R2129.2
ECAT1_TXD3: R1310.1 R2128.2
ECAT1_TXEN: R1305.1 ; also on sheet 17
ECAT_LINK1: J32.14 R1172.2 R1173.1 U123.25(LED1_PHYAD1) ; also on sheet 8
ENET2_MII_COL: R1169.2 R1311.1
ENET2_MII_CRS: R1309.1 R2133.2
ENET4_CARD_DET_B: J134.5 ; also on sheet 9
ENET4_CRS_DV: R1289.1 ; also on sheet 9
ENET4_GPIO: R284.1 TP1061.1(Pin1) ; also on sheet 9
ENET4_INT_B: R1313.1 R2585.2 R2586.2 ; also on sheet 8
ENET4_RGMII_RX_EN: R274.2 ; also on sheet 9
ENET4_RGMII_RXC: R275.2 ; also on sheet 9
ENET4_RGMII_RXD0: R276.2 ; also on sheet 9
ENET4_RGMII_RXD1: R277.2 ; also on sheet 9
ENET4_RGMII_RXD2: R2618.2 ; also on sheet 9
ENET4_RGMII_RXD3: R2619.2 ; also on sheet 9
ENET4_RGMII_TX_EN: R273.2 ; also on sheet 9
ENET4_RGMII_TXC: R272.2 ; also on sheet 9
ENET4_RGMII_TXD0: R271.2 ; also on sheet 9
ENET4_RGMII_TXD1: R2576.2 ; also on sheet 9
ENET4_RGMII_TXD2: R2617.2 ; also on sheet 9
ENET4_RGMII_TXD3: R2616.2 ; also on sheet 9
ENET4_RST_B: R295.2 R1288.1 R2587.2 ; also on sheet 8
ENET4_RXD0: R1290.1 ; also on sheet 9
ENET4_RXD1: R1291.1 ; also on sheet 9
ENET4_RXER: R1292.1 ; also on sheet 9
ENET4_RXER_DC: J134.47 TP1060.1(Pin1) ; also on sheet 9
ENET4_TX_REF_CLK: R1293.1 ; also on sheet 9
ENET4_TXD0: R1295.1 ; also on sheet 9
ENET4_TXD1: R1296.1 ; also on sheet 9
ENET4_TXEN: R1294.1 ; also on sheet 9
ENET4_TXER: J134.55 TP1062.1(Pin1) ; also on sheet 9
ENET_INH: J134.49 R283.2
ENET_INH_B: J134.43 R280.2
ENET_REF_CLK: J134.4 TP1055.1(Pin1)
FlexSPI2_A_CLK: R2131.2 U15.B2(CK)
FlexSPI2_A_D0: R2123.2 U15.D3(DQ0)
FlexSPI2_A_D1: R2126.2 U15.D2(DQ1)
FlexSPI2_A_D2: R2127.2 U15.C4(DQ2)
FlexSPI2_A_D3: R2130.2 U15.D4(DQ3)
FlexSPI2_A_DQS: R333.2 U15.C3(RWDS)
FlexSPI2_A_SS0: R332.2 U15.A3(~{CS})
FlexSPI2_B_CLK: R2122.2 U15.B1(~{CK})
FlexSPI2_B_D0: R2119.2 U15.D5(DQ4)
FlexSPI2_B_D1: R2118.2 U15.E3(DQ5)
FlexSPI2_B_D2: R2115.2 U15.E2(DQ6)
FlexSPI2_B_D3: R2114.2 U15.E1(DQ7)
GPIO_AD_00: R869.1 R1067.1 ; also on sheet 8
GPIO_AD_01: R870.1 R1056.2 ; also on sheet 8
GPIO_AD_02: R736.2 R871.1 R1064.1 ; also on sheet 8
GPIO_AD_03: R733.2 R872.1 R1054.2 ; also on sheet 8
GPIO_AD_04: R731.2 R874.1 R1069.1 ; also on sheet 8 11
GPIO_AD_05: R729.2 R873.1 R1059.2 ; also on sheet 8
GPIO_AD_06: R727.2 R747.1 R1066.1 ; also on sheet 8 26
GPIO_AD_07: R734.2 R749.1 R1057.2 ; also on sheet 8
GPIO_AD_08: R737.2 R1068.1 ; also on sheet 8 26
GPIO_AD_09: R752.2 R760.1 R1058.2 ; also on sheet 8
GPIO_AD_10: R750.2 R1065.1 ; also on sheet 8
GPIO_AD_11: R1055.2 ; also on sheet 8
GPIO_AD_12: R730.2 R1073.1 ; also on sheet 8
GPIO_AD_13: R732.2 R1063.2 ; also on sheet 8
GPIO_AD_14: R1071.1 ; also on sheet 8
GPIO_AD_15: R725.2 R1061.2 ; also on sheet 8 26
GPIO_AD_16: R1072.1 ; also on sheet 8
GPIO_AD_17: R1062.2 ; also on sheet 8
GPIO_AD_18: R724.2 ; also on sheet 8 26
GPIO_AD_19: R726.2 ; also on sheet 8 26
GPIO_AD_21: R1049.1 ; also on sheet 8
GPIO_AD_22: R1051.1 ; also on sheet 8
GPIO_AD_30: R764.1 ; also on sheet 8
GPIO_AD_33: R763.1 ; also on sheet 8
GPIO_AD_34: R767.1 ; also on sheet 8
GPIO_AD_35: R735.1 ; also on sheet 8
GPIO_AON_08: R723.2 ; also on sheet 8 26
GPIO_AON_09: R722.2 ; also on sheet 8 26
GPIO_AON_15: R758.2 ; also on sheet 8
GPIO_AON_16: R759.2 ; also on sheet 8
GPIO_EMC_B1_30_P: R2114.1 R2116.1 ; also on sheet 9
GPIO_EMC_B1_31_P: R2115.1 R2117.1 ; also on sheet 9
GPIO_EMC_B1_32_P: R2118.1 R2120.1 ; also on sheet 9
GPIO_EMC_B1_33_P: R2119.1 R2121.1 ; also on sheet 9
GPIO_EMC_B1_34_P: R2122.1 R2124.1 ; also on sheet 9
GPIO_EMC_B1_35_P: R2123.1 R2125.1 ; also on sheet 9
GPIO_EMC_B1_36_P: R2126.1 R2128.1 ; also on sheet 9
GPIO_EMC_B1_37_P: R2127.1 R2129.1 ; also on sheet 9
GPIO_EMC_B1_38_P: R2130.1 R2132.1 ; also on sheet 9
GPIO_EMC_B1_39_P: R332.1 ; also on sheet 9
GPIO_EMC_B1_40_P: R333.1 R2133.1 ; also on sheet 9
GPIO_EMC_B1_41_P: R1169.1 R2131.1 ; also on sheet 9
GPIO_SD_B1_00: R751.2 ; also on sheet 8 10 26
GPIO_SD_B1_01: R757.2 ; also on sheet 8 10 26
GPIO_SD_B1_02: R755.2 ; also on sheet 8 10 26
GPIO_SD_B1_03: R756.2 ; also on sheet 8 10 26
I2C_SCL_ENET_ID: J134.54 R2579.1
I2C_SDA_ENET_ID: J134.52 R285.1
JTAG_DACK: J37.19 R721.1
JTAG_DE: J37.17 R713.2
JTAG_nSRST: D26.C J37.15 R714.2
JTAG_nTRST: J37.3 R717.2 ; also on sheet 8
JTAG_RTCK: J37.11 R720.1
JTAG_TCK: J37.9 R719.1 ; also on sheet 8 23
JTAG_TDI: J37.5 R716.2 ; also on sheet 8
JTAG_TDO: J37.13 ; also on sheet 8 23
JTAG_TMS: J37.7 R715.2 ; also on sheet 8 23
JTAG_VREF: J37.1 R718.2
LPI2C2_SCL: R2579.2 ; also on sheet 8 14 21 26
LPI2C2_SDA: R285.2 ; also on sheet 8 14 21 26
NETC_ECAT_MDC: R1282.2 R2593.2 U123.22(MDC) ; also on sheet 8 16 17 18 31
NETC_ECAT_MDIO: R1283.2 R2592.2 U123.23(MDIO) ; also on sheet 8 16 17 18 31
OSC_25MHz: R1279.1 ; also on sheet 31
P_ENET4_VDDIO: J134.57 TP1063.1(Pin1)
PHY4_3V3: C522.1 L36.2 R1284.1 R1285.1
PHY4_AVDD33: C519.1 C521.1 R1284.2 U123.7(AVDD33_1) U123.30(AVDD33_2)
PHY4_COL: R1311.2 U123.27(COL)
PHY4_CRS_DV: R1289.2 R1309.2 U123.26(CRS_CRS_DV)
PHY4_LED0_AD0/PMEB: J32.12 R1170.2 R1171.1 U123.24(LED0_PHYAD0_PMEB)
PHY4_MDI0+: C512.1 J32.5(TD+) R1278.2 U123.3(MDI_P0) U124.6(A6)
PHY4_MDI0-: C514.1 J32.6(TD-) R1275.2 U123.4(MDI_N0) U124.4(A4)
PHY4_MDI1+: C513.1 J32.1(RD+) R1277.2 U123.5(MDI_P1) U124.1(A1)
PHY4_MDI1-: C511.1 J32.2(RD-) R1276.2 U123.6(MDI_N1) U124.3(A3)
PHY4_RST_B: C517.1 R1281.1 R1288.2 R1312.2 U123.21(PHYRSTB)
PHY4_RXC: R1297.2 U123.13(RXC)
PHY4_RXD0: R1290.2 R1300.2 U123.9(RXD0)
PHY4_RXD1: R1174.2 R1175.1 R1291.2 R1302.2 U123.10(RXD1)
PHY4_RXD2_INTB: R1287.2 R1301.2 R1313.2 U123.11(RXD2_INTB)
PHY4_RXD3: R1180.2 R1181.1 R1303.2 U123.12(RXD3_CLK_CTL)
PHY4_RXDV: R1176.2 R1177.1 R1298.2 U123.8(RXDV)
PHY4_RXER/FXEN: R1178.1 R1179.2 R1292.2 R1299.2 U123.28(RXER_FXEN)
PHY4_TXC: R1293.2 R1304.2 U123.15(TXC)
PHY4_TXD0: R1295.2 R1307.2 U123.16(TXD0)
PHY4_TXD1: R1296.2 R1306.2 U123.17(TXD1)
PHY4_TXD2: R1308.2 U123.18(TXD2)
PHY4_TXD3: R1310.2 U123.19(TXD3)
PHY4_TXEN: R1294.2 R1305.2 U123.20(TXEN)
PHY4_VDD33: C520.1 R1170.1 R1172.1 R1174.1 R1176.1 R1179.1 R1180.1 R1190.2 R1191.1 R1275.1 R1276.1 R1277.1 R1278.1 R1281.2 R1282.1 R1283.1 R1285.2 R1287.1 U123.14(DVDD33)
PHY4_XTAL1: C516.1 R1280.2 U123.31(CKXTAL1) X6.1
PHY4_XTAL2: C515.1 R1279.2 R1333.2 R1334.2 U123.32(CKXTAL2) X6.3
POR_PIN_RST_B: D26.A ; also on sheet 7 22
RST_TGTMCU_B: J46.1 ; also on sheet 6 22 26
SDRAM_3V3: C107.1 C108.1 C109.1 C110.1 C111.1 C112.1 C113.1 C114.1 C115.1 C118.1 C119.1 C120.1 C121.1 C122.1 C123.1 C124.1 C125.1 L9.2 R320.1 R336.1 U14.1(VDD1) U14.3(VDDQ4) U14.9(VDDQ1) U14.14(VDD3) U14.27(VDD2) U14.43(VDDQ2) U14.49(VDDQ3) U16.1(VDD1) U16.3(VDDQ4) U16.9(VDDQ1) U16.14(VDD3) U16.27(VDD2) U16.43(VDDQ2) U16.49(VDDQ3)
SEMC_A0: TP1065.1(TP) U14.23(A0) U16.23(A0) ; also on sheet 9
SEMC_A1: U14.24(A1) U16.24(A1) ; also on sheet 9
SEMC_A2: U14.25(A2) U16.25(A2) ; also on sheet 9
SEMC_A3: U14.26(A3) U16.26(A3) ; also on sheet 9
SEMC_A4: U14.29(A4) U16.29(A4) ; also on sheet 9
SEMC_A5: U14.30(A5) U16.30(A5) ; also on sheet 9
SEMC_A6: U14.31(A6) U16.31(A6) ; also on sheet 9
SEMC_A7: U14.32(A7) U16.32(A7) ; also on sheet 9
SEMC_A8: U14.33(A8) U16.33(A8) ; also on sheet 9
SEMC_A9: U14.34(A9) U16.34(A9) ; also on sheet 9
SEMC_A10: U14.22(A10/AP) U16.22(A10/AP) ; also on sheet 9
SEMC_A11: U14.35(A11) U16.35(A11) ; also on sheet 9
SEMC_A12: U14.36(A12) U16.36(A12) ; also on sheet 9
SEMC_BA0: TP1067.1(TP) U14.20(BS0) U16.20(BS0) ; also on sheet 9
SEMC_BA1: U14.21(BS1) U16.21(BS1) ; also on sheet 9
SEMC_CAS: U14.17(~{CAS}) U16.17(~{CAS}) ; also on sheet 9
SEMC_CKE: R331.1 R338.1 U14.37(CKE) U16.37(CKE) ; also on sheet 9
SEMC_CLK: R327.1 R337.1 ; also on sheet 9
SEMC_CS0: R320.2 R336.2 U14.19(~{CS}) U16.19(~{CS}) ; also on sheet 9
SEMC_CSX0: TP15.1(TP) ; also on sheet 9
SEMC_D0: TP1066.1(TP) U14.2(DQ0) ; also on sheet 9
SEMC_D1: U14.4(DQ1) ; also on sheet 9
SEMC_D2: U14.5(DQ2) ; also on sheet 9
SEMC_D3: U14.7(DQ3) ; also on sheet 9
SEMC_D4: U14.8(DQ4) ; also on sheet 9
SEMC_D5: U14.10(DQ5) ; also on sheet 9
SEMC_D6: U14.11(DQ6) ; also on sheet 9
SEMC_D7: U14.13(DQ7) ; also on sheet 9
SEMC_D8: U14.42(DQ8) ; also on sheet 9
SEMC_D9: U14.44(DQ9) ; also on sheet 9
SEMC_D10: U14.45(DQ10) ; also on sheet 9
SEMC_D11: U14.47(DQ11) ; also on sheet 9
SEMC_D12: U14.48(DQ12) ; also on sheet 9
SEMC_D13: U14.50(DQ13) ; also on sheet 9
SEMC_D14: U14.51(DQ14) ; also on sheet 9
SEMC_D15: U14.53(DQ15) ; also on sheet 9
SEMC_D16: U16.2(DQ0) ; also on sheet 9
SEMC_D17: U16.4(DQ1) ; also on sheet 9
SEMC_D18: U16.5(DQ2) ; also on sheet 9
SEMC_D19: U16.7(DQ3) ; also on sheet 9
SEMC_D20: U16.8(DQ4) ; also on sheet 9
SEMC_D21: U16.10(DQ5) ; also on sheet 9
SEMC_D22: U16.11(DQ6) ; also on sheet 9
SEMC_D23: U16.13(DQ7) ; also on sheet 9
SEMC_D24: U16.42(DQ8) ; also on sheet 9
SEMC_D25: U16.44(DQ9) ; also on sheet 9
SEMC_D26: U16.45(DQ10) ; also on sheet 9
SEMC_D27: U16.47(DQ11) ; also on sheet 9
SEMC_D28: U16.48(DQ12) ; also on sheet 9
SEMC_D29: U16.50(DQ13) ; also on sheet 9
SEMC_D30: U16.51(DQ14) ; also on sheet 9
SEMC_D31: U16.53(DQ15) ; also on sheet 9
SEMC_DM0: U14.15(LDQM) ; also on sheet 9
SEMC_DM1: U14.39(UDQM) ; also on sheet 9
SEMC_DM2: U16.15(LDQM) ; also on sheet 9
SEMC_DM3: U16.39(UDQM) ; also on sheet 9
SEMC_RAS: U14.18(~{RAS}) U16.18(~{RAS}) ; also on sheet 9
SEMC_RDY: TP14.1(TP) ; also on sheet 9
SEMC_WE: U14.16(~{WE}) U16.16(~{WE}) ; also on sheet 9
SENSOR_3V3: C116.1 C117.1 C902.1 D25.A J37.2 J44.16 J45.4(B2) J45.8(B4) J69.1 J134.1 J134.3 L9.1 L36.1 R295.1 R335.1 R713.1 R715.1 R716.1 R717.1 R718.1 R2585.1 TP51.1(Pin1) U15.B4(VCC) U15.D1(VCCQ1) U15.E4(VCCQ2) ; also on sheet 2 5 6 7 8 9 10 11 12 13 14 15 16 17 18 19 20 21 22 23 24 25 26 31
WAKE_IN_OUT: J134.51 R284.2
N99838171: D25.C R714.1
N101094010: R327.2 U14.38(CLK)
N101094248: R337.2 U16.38(CLK)
N102038478: J39.6(B3) R725.1
N102038480: J39.10(B5) R730.1
N102038482: J39.12(B6) R732.1
N102038508: J39.14(B7) R734.1
N102038510: J39.16(B8) R737.1
N102038514: J39.2(B1) R722.1
N102038516: J39.4(B2) R723.1
N102038763: J39.8(B4) R727.1
N102039011: J39.3(A2) R728.1
N102039036: R728.2 R735.2 R738.1
N102040284: J44.2 R750.1
N102040286: J44.4 R752.1
N102040306: J44.10 R756.1
N102040308: J44.8 R755.1
N102040310: J44.12 R757.1
N102040312: J44.6 R751.1
N102040383: J44.18 R758.1
N102040397: J44.20 R759.1
N102051556: J44.5 R753.2
N102051558: J44.1 R746.2
N102051560: J44.3 R748.2
N102051598: J44.7 R760.2
N102051600: J44.9 R764.2
N102051892: C293.1 R746.1 R747.2 R1049.2
N102051905: C294.1 R748.1 R749.2
N102051907: C295.1 R753.1 R1051.2
N102052693: J41.12(B6) R724.1
N102052753: J41.2(B1) R736.1
N102052757: J41.4(B2) R733.1
N102052761: J41.6(B3) R731.1
N102052765: J41.8(B4) R729.1
N102052856: J41.10(B5) R726.1
N102054567: J45.15(A8) R869.2
N102054918: J45.3(A2) R762.1
N102054920: J45.1(A1) R766.1
N102054973: R765.1 R766.2 R767.2
N102055690: R761.1 R762.2 R763.2
N102055791: J45.5(A3) R874.2
N102055814: J45.7(A4) R873.2
N102055853: J45.9(A5) R872.2
N102055876: J45.11(A6) R871.2
N102055899: J45.13(A7) R870.2
N102056178: D27.C J45.10(B5)
N102056760: J45.6(B3) J46.2
N105216901: J69.3 R1067.2
N105216903: J69.5 R1064.2
N105216905: J69.7 R1069.2
N105216907: J69.9 R1066.2
N105216909: J69.11 R1068.2
N105216911: J69.13 R1065.2
N105216913: J69.15 R1073.2
N105216915: J69.17 R1071.2
N105216917: J69.19 R1072.2
N105217449: J69.4 R1056.1
N105217451: J69.6 R1054.1
N105217453: J69.8 R1059.1
N105217455: J69.10 R1057.1
N105217467: J69.12 R1058.1
N105217469: J69.14 R1055.1
N105217471: J69.16 R1063.1
N105217473: J69.18 R1061.1
N105217475: J69.20 R1062.1
N105572670: J32.11 R1191.2
N105572737: C507.1 J32.4(TCT)
N105572739: C508.1 J32.3(RCT)
N105593482: J32.13 R1190.1
N105605244: C518.1 U123.2(AVDD10OUT)
N105605262: C510.1 U123.29(DVDD10OUT)
N105605885: R1286.2 U123.1(RSET)
N106615195: R335.2 U15.A4(~{RESET})
N107431851: J32.10(VC1-) TP1071.1(TP)
N107431853: J32.9(VC1+) TP1070.1(TP)
N107755006: J134.19 TP1056.1(Pin1)
N107755030: J134.27 TP1057.1(Pin1)
N107755069: J134.41 TP1058.1(Pin1)
N107755071: R280.1 R283.1 TP1059.1(Pin1)
N107755107: J134.56 R2586.1
N107755114: J134.58 TP1064.1(Pin1)
N107755120: C887.1 J134.59 R2584.2
N107755122: J134.60 R2587.1

Not connected (* = marked no-connect by the designer): J32 7(NC)* 8(NC)*; J39 1(A1)* 5(A3)* 7(A4)* 9(A5)* 11(A6)* 13(A7)* 15(A8)*; J41 5(A3)* 7(A4)* 9(A5)* 11(A6)*; J45 2(B1)*; J134 7* 9* 13* 15* 23* 31* 35* 37*; U14 40(NC)*; U15 A2(RFU1)* A5(RFU2)* B5(RFU3)* C2(RFU4)* C5(RFU5)*; U16 40(NC)*; U124 5(A5)*

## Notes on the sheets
sheet 27
- JTAG(SWD)
- FLEXIO HEADER
- Both JTAG and SWD are supported for debug
- JTAG_PWR
- FLEXIO2_FLEXIO00
- FLEXIO2_FLEXIO01
- FLEXIO2_FLEXIO02
- FLEXIO2_FLEXIO03
- SWD_CLK
- FLEXIO2_FLEXIO04
- FLEXIO2_FLEXIO05
- FLEXIO2_FLEXIO06
- FLEXIO2_FLEXIO07
- SWDIO
- FLEXIO2_FLEXIO08
- FLEXIO2_FLEXIO10
- FLEXIO2_FLEXIO09
- FLEXIO2_FLEXIO11
- FLEXIO2_FLEXIO12
- FLEXIO2_FLEXIO13
- FLEXIO2_FLEXIO14
- FLEXIO2_FLEXIO15
- FLEXIO2_FLEXIO16
- FLEXIO2_FLEXIO17
- Arduino&MC Interface
- D0/UART_RX
- D1/UART_TX
- ENC_I
- D2/INT0
- D3/INT1/PWM/OC2B
- A4/ADC4/SDA
- A5/ADC5/SCL
- D4/T0/XCK
- A3/ADC3
- D5/TI/PWM
- A2/ADC2
- D6/AIN0/PWM/OC0A
- A1/ADC1
- D7/AIN1
- A0/ADC0
- (ADC2_CH1B)
- (ADC1_CH5A)
- (ADC1_CH5B)
- D8/CLKO/ICP1
- CUR_A
- D9/OC1A/PWM
- CUR_B
- PWM_AT
- VIN
- D10/SPI_CS/PWM
- CUR_C
- (ADC2_CH2A)
- PWM_AB
- D11/OC2A/PWM/SPI_MOSI
- VOLT_DCB
- PWM_BT
- D12/SPI_MISO
- D13/SPI_CLK
- CUR_DCB
- PWM_BB
- PWM_CT
- 3V3
- 5V
- PWM_CB
- RESET_b
- POR_B
- AREF
- ENC_A
- IOREF
- D14/I2C_SDA
- ENC_B
- D15/I2C_SCL
sheet 28
- SDRAM
- 4 M*4 BANKS*16 BITS SDRAM = 256Mb
- 4 M*4 BANKS*16 BITS SDRAM = 256Mb
- Signal Multiplex
- HyperRAM(64Mb)
sheet 29
- Only support 3.3V ENET IO daughter cards
- ETH4 RGMII/MII/RMII DC
- Daughter Card List
- 1. TJA1103SDB(Default)
  2. SJA1105Q-EVB
- ENET Connector Spec.
- Pin Number
- RGMII Mode
- RMII Mode
- MII Mode
- 8
  10
  14
  16
  20
  24
  28
  32
  36
  38
  42
  44
  47
  48
  50
  55
- RGMII_TD3
  RGMII_TD2
  RGMII_TD1
  RGMII_TD0
  RGMII_TXC
  RGMII_TX_CTL
  RGMII_RX_CTL
  RGMII_RXC
  RGMII_RD0
  RGMII_RD1
  RGMII_RD2
  RGMII_RD3
  --
  RGMII_MDIO
  RGMII_MDC
  --
- --
  --
  MII_TXD1
  MII_TXD0
  MII_REFCLK
  MII_TXEN
  MII_CRS_DV
  MII_RXC
  MII_RXD0
  MII_RXD1
  --
  --
  MII_RXER
  MII_MDIO
  MII_MDC
  --
- MII_TXD3
  MII_TXD2
  MII_TXD1
  MII_TXD0
  MII_REFCLK
  MII_TXEN
  MII_RX_DV
  MII_RXC
  MII_RXD0
  MII_RXD1
  MII_RXD2
  MII_RXD3
  MII_RXER
  MII_MDIO
  MII_MDC
  MII_TXER
sheet 30
- 10/100Mbps Ethernet Circuit
- ESD PROTECTION
- RXD3(RMII REF_CLK Direction)
  REF_CLK Input mode:1(Default)
  REF_CLK Output mode: 0
- RXD1(WOL/LED)
  WOL: 1
  LED: 0(Default)
- RXDV(MII/RMII Mode Config)
  RMII mode:1 (Default)
  MII mode: 0
- LED0_AD0=1, LED1_AD1=1
  Without WOL :
  PHY Address can be 0x00000 - 0x00011
  With WOL :
  PHY Address only can be 0x00001 & 0x00011
- RXER/FXEN(UTP/Fiber Config)
  Fiber mode:1
  UTP mode: 0(Default)
- Differential 100ohm
  Difference tolerance 100mil
- Differential 100ohm
  Difference tolerance 100mil
- Note:
  No POE function supported.
- RMII Interface(Default)
- MII Interface
- 1. Change RXDV(MII/RMII Mode Config)
  2. Resistor rework
